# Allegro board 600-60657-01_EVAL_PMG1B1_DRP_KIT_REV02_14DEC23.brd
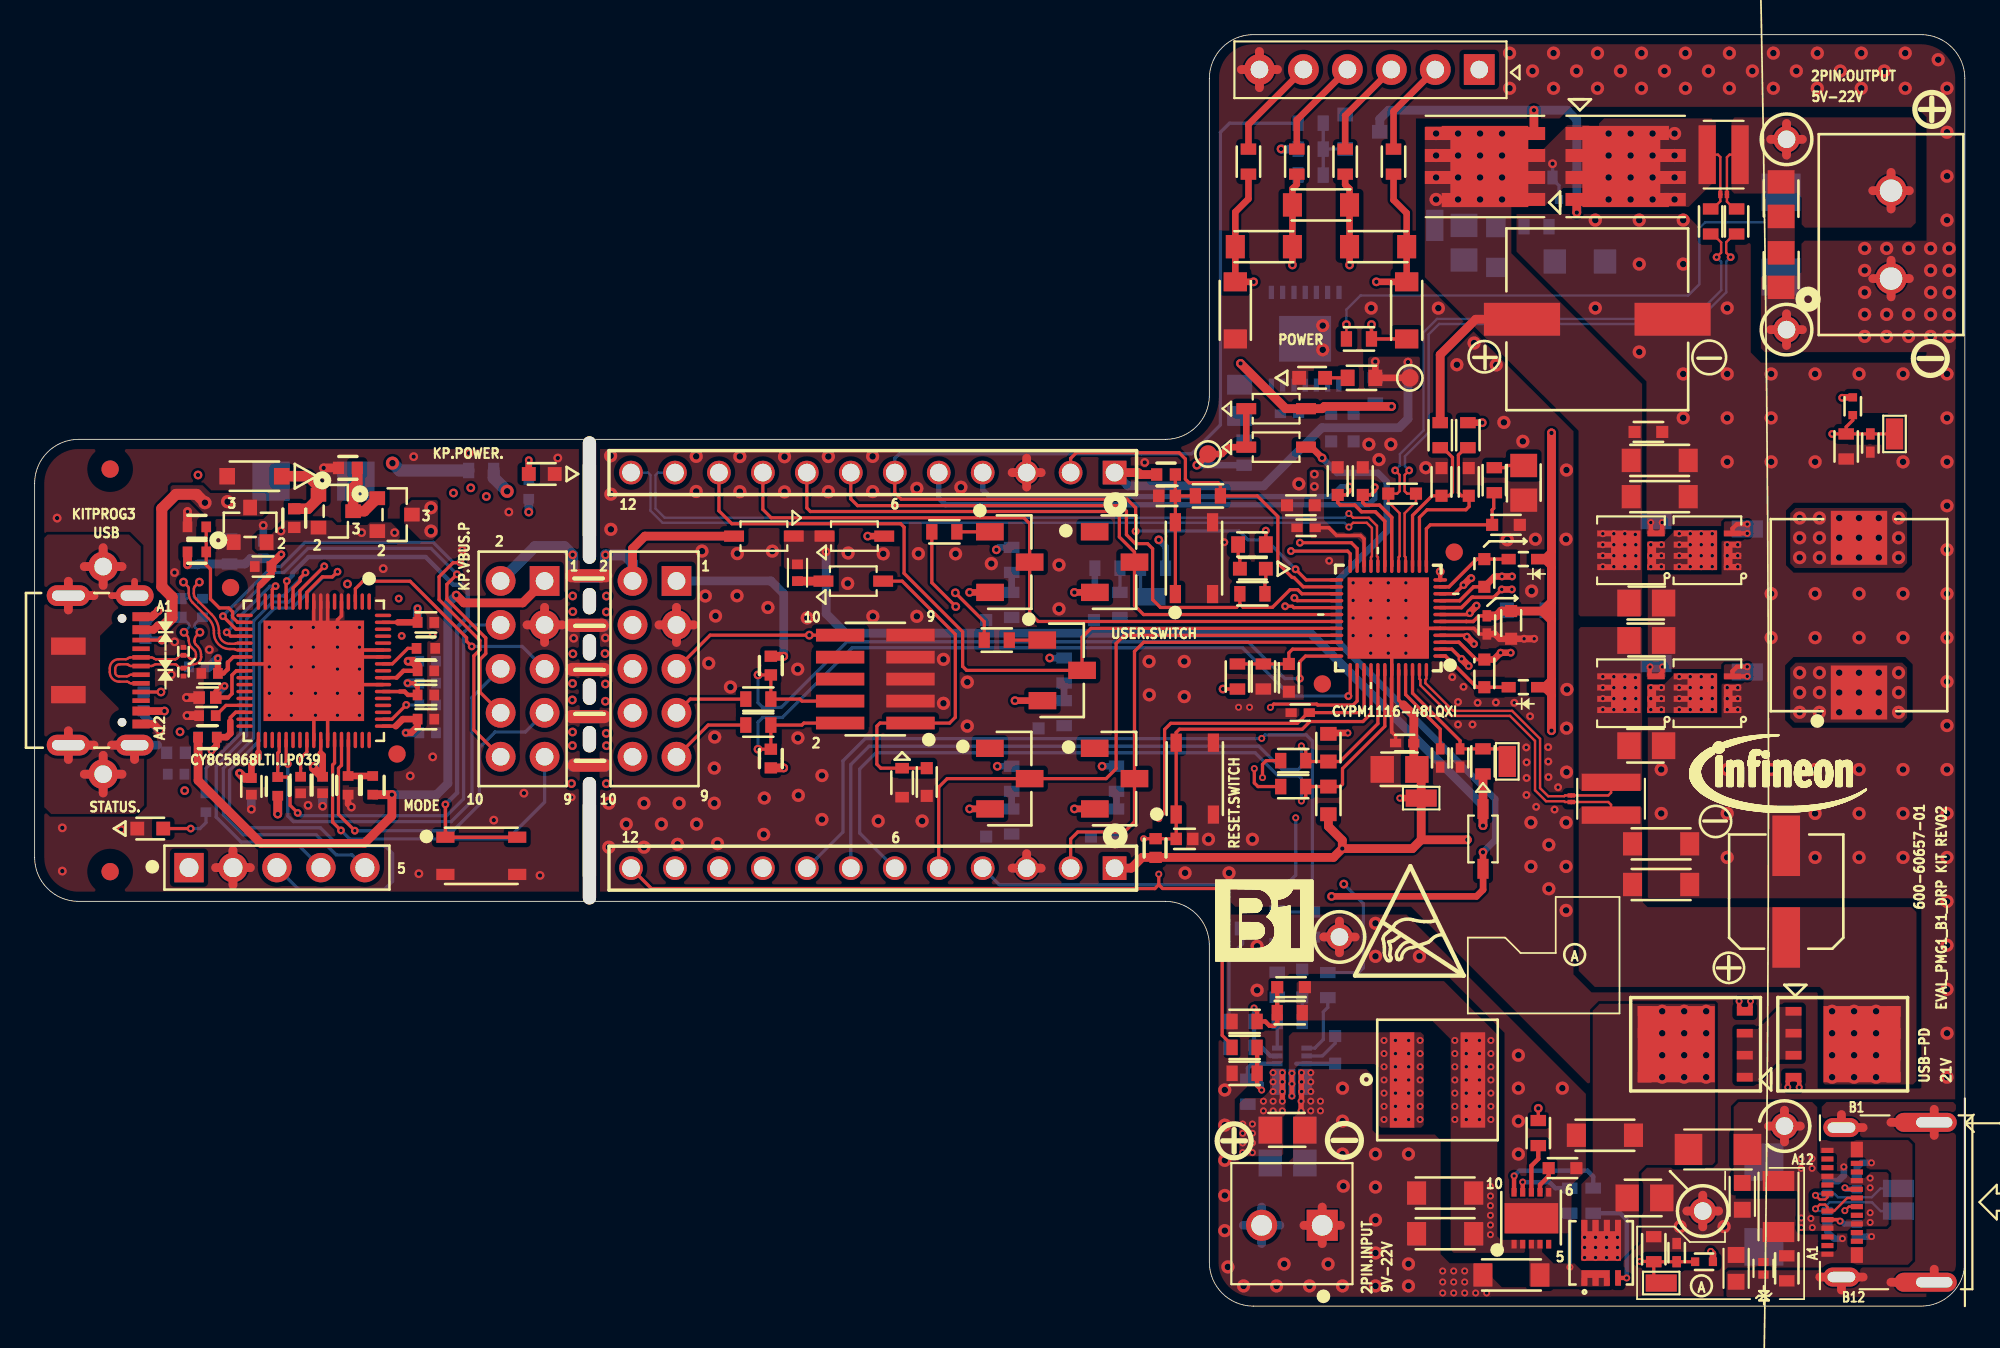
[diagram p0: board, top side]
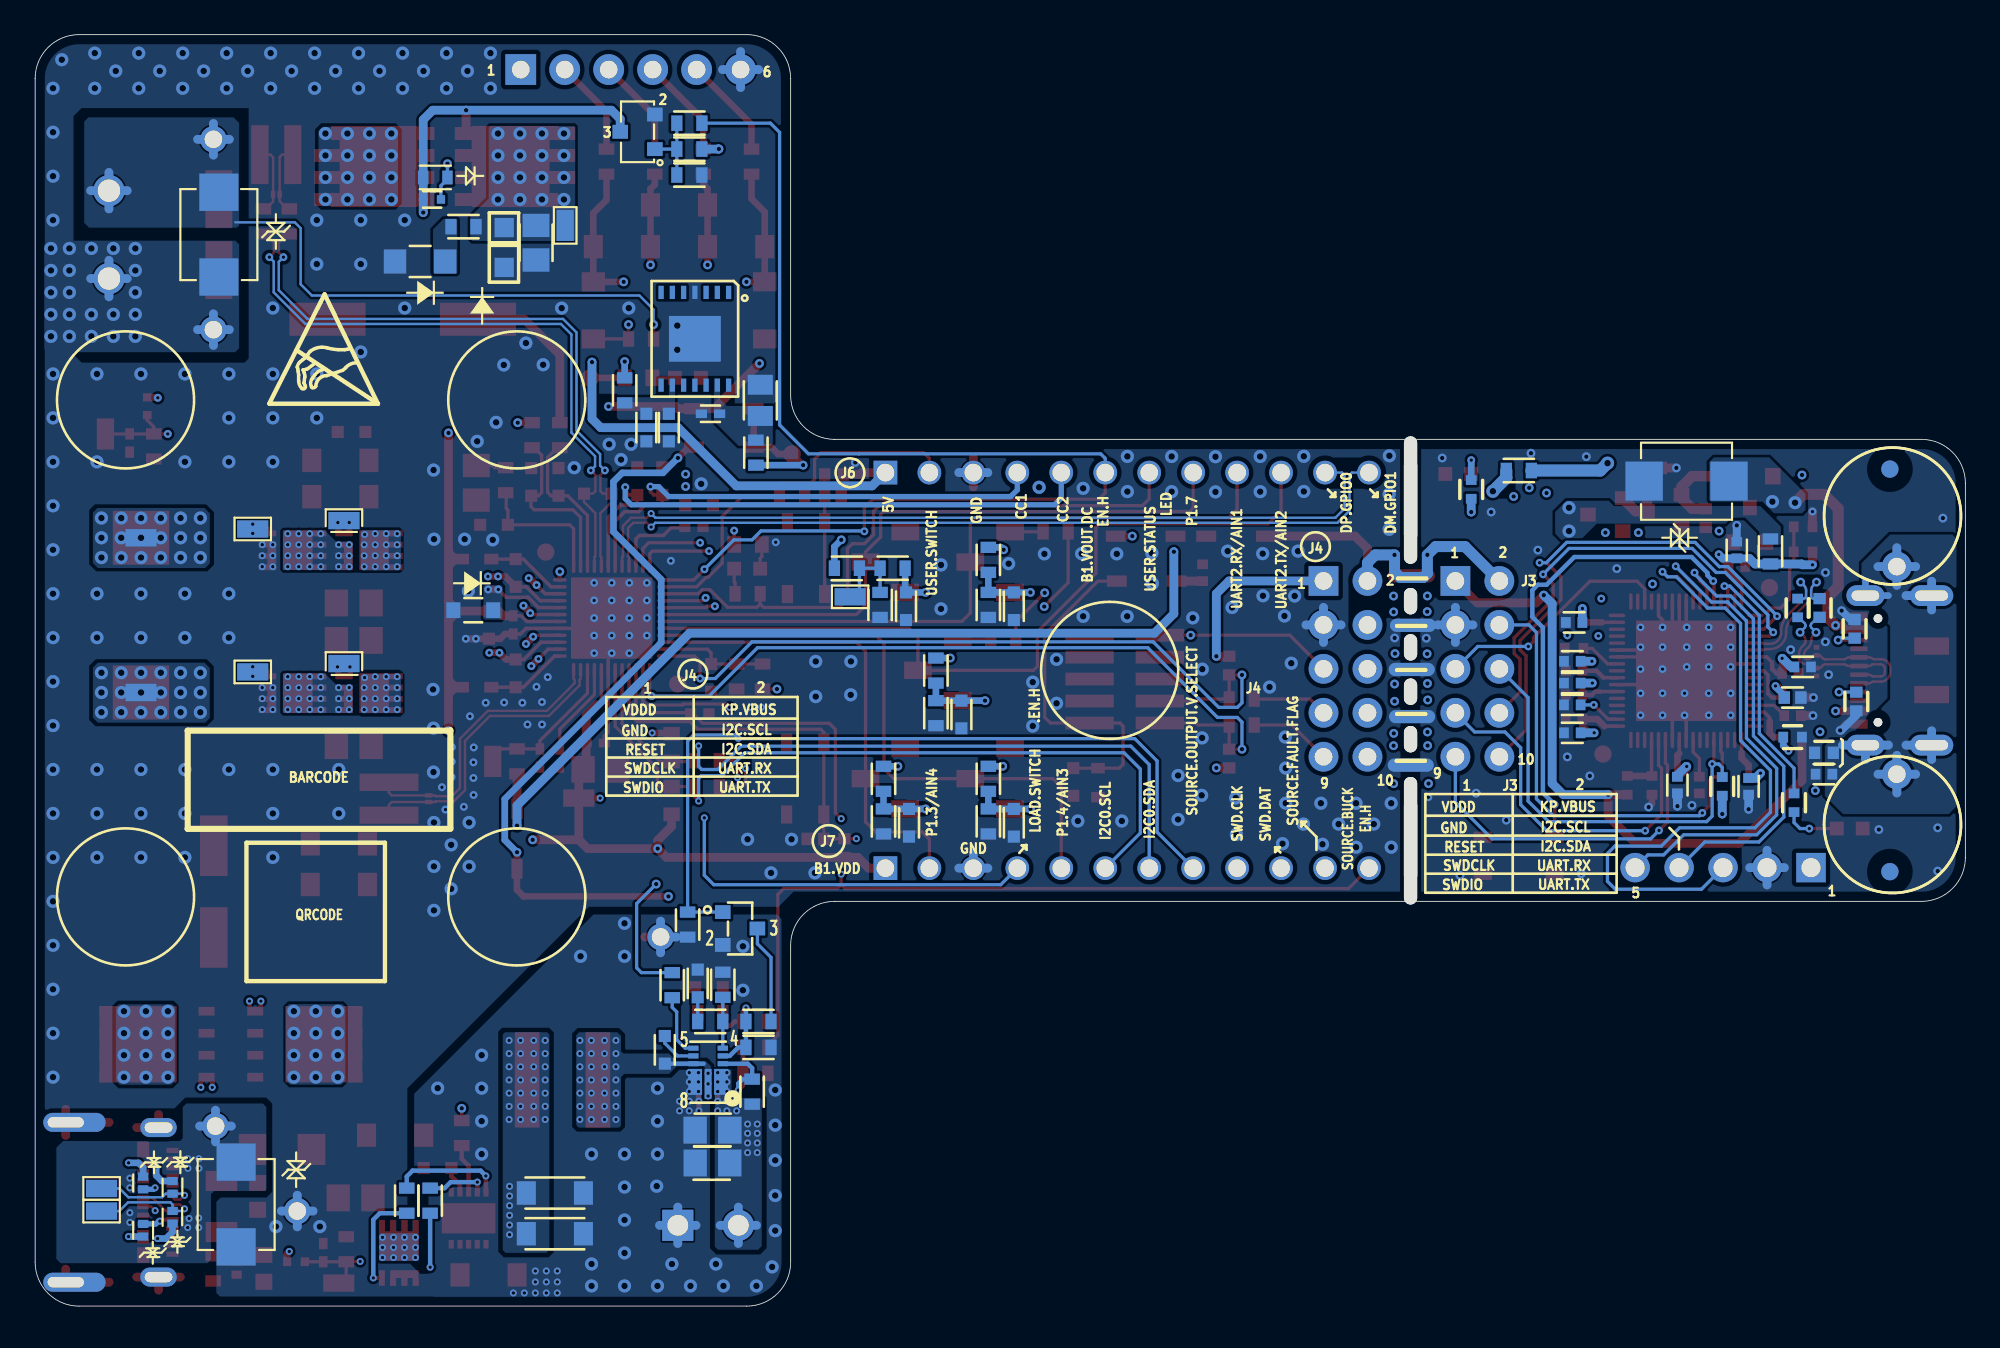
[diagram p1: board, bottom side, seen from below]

Outline 111.52 x 73.48 mm; copper layers: TOP, GND, PWR/SIG, BOTTOM. Coordinates in mm from the lower left corner of the outline.
Outline path: 0,47.55 0,25.93 arc(0.74,24.14) 2.54,23.39 65.33,23.39 arc(67.13,22.65) 67.87,20.85 67.87,2.54 arc(68.62,0.74) 70.41,0 108.98,0 arc(110.78,0.74) 111.52,2.54 111.52,70.94 arc(110.78,72.74) 108.98,73.48 70.41,73.48 arc(68.62,72.74) 67.87,70.94 67.87,52.63 arc(67.13,50.84) 65.33,50.09 2.54,50.09 arc(0.74,49.35) 0,47.55

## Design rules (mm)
constraint set DEFAULT: min track width 0.188, pair gap 0.152
net group CSIOUT_CS_0: nets CSNO CSPO
net group DIFFPAIR0: nets KP_DM KP_DP
net group DIFFPAIR1: nets DM_GPIO1 DP_GPIO0
net group DP1: nets N19965162 N19965164
net group POWER_PH: nets P5LP_VCCD VTARG_MEAS
net group SENSE1: nets IIN_CSN IIN_CSP
net group C: nets UART_CTS
nets with their own width: min track width 0.635; nets KP_VBUS_P P5LP_VDD

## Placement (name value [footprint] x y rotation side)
C1  1.0 uF  [CAPC1005_0402N]  9.98 34.13 180 top
C2  1.0 uF  [CAPC1005_0402N]  10.11 36.57 180 top
C3  0.1uF  [CAPC1005_0402N]  12.52 30.04 270 top
C4  1.0 uF  [CAPC1005_0402N]  13.2 42.74 180 top
C5  1.0 uF  [CAPC1005_0402N]  15.37 30.11 270 top
C6  0.1uF  [CAPC1005_0402N]  16.64 30.11 270 top
C7  0.1uF  [CAPC1005_0402N]  22.61 39.51 0 top
C8  0.1uF  [CAPC1005_0402N]  22.61 36.72 0 top
C9  1.0 uF  [CAPC1005_0402N]  22.71 36.01 0 bottom
C10  1.0 uF  [CAPC1005_0402N]  22.61 33.92 0 top
C11  1uF  [CAPC1608X90N_TY]  51.55 30.29 90 top
C12  0.1uF  [CAPC1005_0402N]  65.43 46.83 0 top
C13  0.1uF  [CAPC1005_0402N]  66.44 27 180 top
C14  0.1uF  [CAPC1608X90N_TY]  74.91 50.77 270 bottom
C15  22uF  [CAPC1608X90N_TY]  76.21 50.77 270 bottom
C16  10uF  [CAPC3216X180N_TDK]  81.49 4.19 180 bottom
C17  1uF  [CAPC1608X90N_TY]  73.16 46.28 180 top
C18  12pF  [CAPC1608X90N_TY]  72.59 18.43 0 top
C19  4.7uF  [CAPC2012X70N_MURATA]  72.39 10.17 0 top
C20  0.1uF  [CAPC1005X56N_CYPS]  73.46 44.98 0 top
C21  0.1uF  [CAPC1005X56N_CYPS]  73.12 34.3 180 top
C22  390pF  [CAPC1608X90N_TY]  75.29 47.68 90 top
C23  0.1uF  [CAPC1005X56N_CYPS]  72.5 51.57 180 bottom
C24  10uF  [CAPC2012_0805N]  69.63 52.35 270 bottom
C25  390pF  [CAPC1608X90N_TY]  76.74 47.68 90 top
C26  10uF  [CAPC2012X70N_MURATA]  78.86 31.02 180 top
C27  0.1uF  [CAPC1608X90N_TY]  79.01 46.96 0 top
C28  0.1uF  [CAPC1005X56N_CYPS]  79.16 32.54 0 top
C29  0.1uF  [CAPC1005X56N_CYPS]  81.21 31.68 90 top
C30  0.1uF  [CAPC1608X90N_TY]  81.28 47.63 90 top
C31  0.1uF  [CAPC1005X56N_CYPS]  82.36 31.68 90 top
C32  10uF  [CAPC3216X180N_TDK]  81.49 6.54 180 top
C33  10uF  [CAPC3216X180N_TDK]  81.49 4.19 180 top
C34  0.1uF  [CAPC1608X90N_TY]  82.86 47.63 90 top
C35  0.1uF  [CAPC1608X90N_TY]  83.76 42.37 270 top
C36  0.1uF  [CAPC1608X90N_TY]  83.76 36.57 270 top
C37  1uF  [CAPC1608X90N_TY]  85.31 39.37 270 top
C38  0.1uF  [CAPC1608X90N_TY]  85.01 45.15 0 top
C39  100nF  [CAPC2012X70N_MURATA]  86.03 47.58 270 top
C40  10uF  [CAPC3216X180N_TDK]  85.33 1.8 180 top
C41  100 pF  [CAPC1608X90N_TY]  88.28 7.98 0 top
C42  1uF  [CAPC2012X70N_MURATA]  93.11 40.63 0 top
C43  1uF  [CAPC2012X70N_MURATA]  93.11 38.47 0 top
C44  1uF  [CAPC2012X70N_MURATA]  93.11 32.39 0 top
C45  0.1uF  [CAPC1608X90N_TY]  93.24 50.52 0 top
C46  10uF  [CAPC3216X180N_TDK]  93.89 48.87 0 top
C47  10uF  [CAPC3216X180N_TDK]  93.89 46.78 0 top
C48  10uF  [CAPC3216X180N_TDK]  93.97 26.71 0 top
C49  10uF  [CAPC3216X180N_TDK]  93.97 24.36 0 top
C50  4.7uF  [CAPC2012X70N_MURATA]  93.01 6.25 0 top
C51  220uF  [CAP_PC_10X12P4_WE]  90.28 57.03 180 top
C52  1nF  [CAPC1005X56N_CYPS]  94.87 3.09 270 top
C53  10nF  [CAPC1608X90N_A]  98.31 2.18 270 top
C54  10nF  [CAPC1608X90N_A]  98.66 6.34 270 top
C55  100uF  [CAP_PC_6P30X8_UCC]  101.2 23.96 270 top
C56  10uF  [CAPC3216X190N_A]  100.76 5.76 270 top
C57  1uF  [CAPC2012X70N_MURATA]  100.91 63.97 270 top
C58  1uF  [CAPC2012X70N_MURATA]  100.91 59.88 270 top
C59  1nF  [CAPC1005X56N_CYPS]  106.06 49.88 90 top
C60  10uF  [CAPC3216X180N_TDK]  81.49 6.54 180 bottom
C61  0.1uF  [CAPC1608X90N_TY]  75.14 14.81 90 bottom
C62  1.2nF  [CAPC1608X90N_TY]  73.24 18.65 90 bottom
C63  4.7uF  [CAPC2012X70N_MURATA]  72.39 10.17 0 bottom
C64  4.7uF  [CAPC2012X70N_MURATA]  72.39 8.27 0 bottom
C65  1.0 uF  [CAPC1005_0402N]  22.61 39.51 0 bottom
C66  1.0 uF  [CAPC1005_0402N]  22.71 37.27 0 bottom
C67  0.1uF  [CAPC1005_0402N]  22.61 35.32 0 top
C68  1.0 uF  [CAPC1005_0402N]  22.71 33.13 0 bottom
C69  1.0 uF  [CAPC1005_0402N]  22.71 34.75 0 bottom
C70  0.1uF  [CAPC1005_0402N]  16.64 30.11 270 bottom
C71  0.1uF  [CAPC1005_0402N]  13.21 43.69 90 bottom
C72  1.0 uF  [CAPC1005_0402N]  12.52 30.04 270 bottom
C73  0.1uF  [CAPC1005_0402N]  9.4 36.94 180 bottom
C74  10nF  [CAPC1005_0402N]  8.17 30.74 0 bottom
C75  0.1uF  [CAPC1005X56N_CYPS]  83.9 39.37 90 top
C76  1.0 uF  [CAPC1005_0402N]  9.98 35.17 180 bottom
C77  0.1uF  [CAPC1005_0402N]  9.98 35.17 180 top
C78  1uF  [CAPC2012X70N_MURATA]  82.58 61.46 270 bottom
C79  10nF  [CAPC1608X90N_TY]  54.98 40.45 270 bottom
C80  10nF  [CAPC1608X90N_TY]  58 34.19 270 bottom
C81  10nF  [CAPC1608X90N_TY]  54.98 27.94 270 bottom
C82  10nF  [CAPC1608X90N_TY]  61.03 27.94 270 bottom
C83  10nF  [CAPC1608X90N_TY]  72.47 36.31 270 top
C84  0.1uF  [CAPC1608X90N_TY]  61.21 40.45 270 bottom
C85  0.1uF  [CAPC3216X180N_TDK]  77.62 61.23 180 top
C86  0.1uF  [CAPC3216X180N_TDK]  74.32 63.64 180 top
C87  0.1uF  [CAPC3216X180N_TDK]  71.02 61.23 180 top
C88  0.1uF  [CAPC3216X180N_TDK]  69.37 57.55 270 top
C89  0.1uF  [CAPC3216X180N_TDK]  79.27 57.55 90 top
C90  10uF  [CAPC3216X180N_TDK]  90.73 9.88 180 top
D1  ESD131-B1-W0201  [ESD0201_CANTRON]  8.6 37.84 270 top
D2  ESD131-B1-W0201  [ESD0201_CANTRON]  8.6 36.64 90 top
D3  MMSZ5230C-E3-08  [SOD-123_DI]  12.7 47.96 0 top
D4  CMHSH5-4 TR PBFREE  [DIO2_SOD123N]  42.14 44.5 180 top
D5  CMHSH5-4 TR PBFREE  [DIO2_SOD123N]  47.36 44.5 0 top
D6  CMHSH5-4 TR PBFREE  [DIO2_SOD123N]  47.3 41.9 0 top
D7  -  [BZT52C24T-7]  88.4 65.23 0 bottom
D8  RB510SM-40T2R  [SOD-523]  86.01 43.17 0 top
D9  RB510SM-40T2R  [SOD-523]  86.01 35.77 0 top
D10  SZESD7241N2T5G  [DIODFN100X60X45-2N]  99.88 2.18 90 top
D11  SZESD7241N2T5G  [DIODFN100X60X45-2N]  103.58 5.13 90 bottom
D12  SZESD7241N2T5G  [DIODFN100X60X45-2N]  103.58 6.86 270 bottom
D13  SZESD7241N2T5G  [DIODFN100X60X45-2N]  105.28 7.11 270 bottom
D14  SZESD7241N2T5G  [DIODFN100X60X45-2N]  105.28 4.38 90 bottom
D15  SMBJ24CA  [DIOM5336X262N]  100.91 61.92 90 bottom
D16  SMBJ24CA  [DIOM5336X262N]  99.91 5.87 90 bottom
D17  CMHSH5-4 TR PBFREE  [DIO2_SOD123N]  83.68 27 270 top
D18  CMHSH5-4 TR PBFREE  [DIO2_SOD123N]  71.73 49.64 0 top
D19  CMHSH5-4 TR PBFREE  [DIO2_SOD123N]  71.73 51.86 0 top
D20  SMBJ24CA  [DIOM5336X262N]  16.11 47.67 180 bottom
D21  BZD27B22P-M3-08  [DO-219AB]  89.28 60.37 180 bottom
D22  DF2S23P2FU  [SOD-323]  84.42 61.18 90 bottom
D23  PLZ24B-G3/H  [DO-219AC]  86.21 40.22 180 bottom
DM_GPIO1  SMD  [SMDTP]  107.68 6.8 180 bottom
DP_GPIO0  SMD  [SMDTP]  107.68 5.49 180 bottom
FB1  50 OHMS@100MHz  [IND1206N]  97.26 9.05 180 top
HG1  SMD  [SMDTP]  93.68 37.14 180 bottom
HG2  SMD  [SMDTP]  93.68 45.4 180 bottom
J1  DX07S016JA3R1500  [JAE_DX07S016JA3R1500]  2.8 36.74 270 top
J2  5 PIN PROG  [WURTH_61300511121]  8.92 25.34 0 top
J3  CON 5x2  [SULLINS_PPPC052LFBN-RC]  29.47 41.91 270 top
J4  CON 5x2  [SULLINS_PPPC052LFBN-RC]  37.09 41.91 270 top
J6  TSW-112-14-G-S  [SAMTEC_TSW-112-14-G-S]  62.4 48.17 180 top
J7  TSW-112-14-G-S  [SAMTEC_TSW-112-14-G-S]  62.4 25.31 180 top
J8  50MIL KEYED SMD  [SAMTEC_FTSH-105-01-L-DV-K]  50.6 33.7 90 top
J9  691213510002  [CONN_691213510002_WRE]  107.26 59.38 90 top
J10  2012670005  [MOLEX_2012670005]  111.52 6 90 top
J11  691103110002  [TE_1776275-2]  74.39 4.67 180 top
J13  61300611121  [BERG_2P54P_1X6N]  77.18 71.45 270 top
JMP1  USB_Hold  [CON_RA_STIFF_850P_TYPEC]  3.96 30.74 90 top
L1  15uH  [IND_XGL6060-682MEC_COC-M]  81.05 13.07 0 top
L2  6.8uH  [MPX1D1040L6R8]  105.41 39.93 90 top
LED1  AMBER LED  [LEDC1608_0603N]  6.68 27.6 180 top
LED2  AMBER LED  [LEDC1608_0603N]  29.3 48.09 0 top
LED3  GREEN  [LEDC1608X80N_G]  70.38 42.62 0 top
LED4  GREEN  [LEDC1608X80N_G]  73.81 53.65 180 top
LG1  SMD  [SMDTP]  98.95 36.65 0 bottom
LG2  SMD  [SMDTP]  98.95 44.91 180 bottom
NOREF  -  []  6.1 41.21 0 top
NOREF#2  -  []  0.51 24.41 0 top
NOREF#3  -  []  2.54 50.09 0 top
NOREF#4  -  [unnamed#2]  32.06 40.74 0 top
NOREF#5  -  []  8.16 37.21 0 top
NOREF#6  -  []  69.56 70.07 0 top
NOREF#7  -  []  0 25.93 90 top
NOREF#8  -  [unnamed#2]  32.06 45.95 0 top
NOREF#9  -  [unnamed#2]  32.06 38.07 0 top
NOREF#10  -  [unnamed#2]  32.06 47.22 0 top
NOREF#11  -  [unnamed#2]  32.06 26.26 0 top
NOREF#12  -  []  70.41 0 0 top
NOREF#13  -  []  5.05 33.74 90 top
NOREF#14  -  []  15.04 34.61 90 top
NOREF#15  -  [unnamed#2]  32.06 27.53 0 top
NOREF#16  -  []  -317.2 -204.42 0 top
NOREF#17  -  []  94.53 76.73 0 top
NOREF#18  -  []  1.95 41.06 0 top
NOREF#19  -  [unnamed#2]  32.06 32.77 0 top
NOREF#20  -  []  8.46 37.55 90 top
NOREF#21  -  []  1.95 35.34 90 top
NOREF#22  -  []  1.95 32.42 90 top
NOREF#23  -  []  80.93 71.46 0 top
NOREF#24  -  []  2.54 23.39 0 top
NOREF#25  -  []  8.74 36.93 90 top
NOREF#26  -  [unnamed#2]  32.06 35.51 0 top
NOREF#27  -  []  70.41 73.48 0 top
NOREF#28  -  []  8.6 37.61 90 top
NOREF#29  -  []  -16.36 -25.12 0 top
NOREF#30  -  []  69.56 70.07 90 top
NOREF#31  -  []  110.41 73.04 0 top
NOREF#32  -  []  111.52 2.54 90 top
NOREF#33  -  []  8.6 36.41 90 top
NOREF#34  -  []  87.88 38.79 0 top
NOREF#35  -  []  7.88 37.83 0 top
NOREF#36  -  [unnamed#2]  4.36 48.37 90 top
NOREF#37  -  [unnamed#2]  4.36 25.11 270 top
NOREF#38  -  [unnamed#2]  4.36 25.11 90 bottom
NOREF#39  -  [unnamed#2]  4.36 48.37 270 bottom
NOREF#40  -  []  12.85 31.29 180 bottom
NTC0  R, NTC  [RESC1608X55N_PEC]  93.55 3.29 270 top
NTC1  R, NTC  [RESC1608X55N_PEC]  104.66 49.68 90 top
NTCP0  SMD  [SMDTP]  93.98 1.33 180 top
NTCP1  SMD  [SMDTP]  107.46 50.41 270 top
Q1  BSS308PEH6327XTSA1  [SOT95P240X111-3N]  12.45 45.15 0 top
Q2  BSS308PEH6327XTSA1  [SOT95P240X111-3N]  17.4 45.94 270 top
Q3  BSS308PEH6327XTSA1  [SOT95P240X111-3N]  20.8 45.74 270 top
Q4  -  [2N7002H6327XTSA2]  76.72 67.87 90 bottom
Q5  BSC084P03NS3GATMA1  [BSC030P03NS3]  83.8 65.86 180 top
Q6  BSZ0589NSATMA1  [PG-TSDSON-8-33]  90.51 3.08 90 top
Q7  -  [BSZ063N04LS6]  92.23 43.68 180 top
Q8  -  [BSZ063N04LS6]  92.23 35.42 180 top
Q9  BSC084P03NS3GATMA1  [BSC030P03NS3]  91.92 65.86 0 top
Q10  -  [BSZ063N04LS6]  96.65 43.68 180 top
Q11  -  [BSZ063N04LS6]  96.65 35.42 180 top
Q12  ISC045N03L5SATMA1  [IFX-PG-TDSON-8-6-V]  95.91 15.14 180 top
Q13  ISC045N03L5SATMA1  [IFX-PG-TDSON-8-6-V]  104.51 15.14 0 top
Q14  2N7002H6327XTSA2  [SOT23_1_2_3]  70.79 21.82 270 bottom
R1  30K  [RESC1005_0402M]  9.37 45.04 0 top
R2  15K  [RESC1005_0402M]  9.37 43.59 0 top
R3  1M  [RESC1005_0402M]  9.98 32.88 0 top
R4  4.7K  [RESC1005_0402M]  14.05 30.04 270 top
R5  1K  [RESC1005_0402M]  15 45.54 270 top
R6  10K  [RESC1005_0402M]  18.1 48.44 180 top
R7  49.9K  [RESC1005_0402M]  18.11 30.1 90 top
R8  49.9K  [RESC1005_0402M]  19.53 30.1 90 top
R9  100K  [RESC1005_0402M]  22.61 38.01 180 top
R10  0 OHM  [RESC1608_0603N]  41.81 35.08 0 top
R11  0 OHM  [RESC1608_0603N]  41.81 33.58 0 top
R12  2.2K  [RESC1005_0402M]  42.54 37.02 90 top
R13  2.2K  [RESC1005_0402M]  42.54 31.64 270 top
R14  0OHM  [RESC1005X40N_PEC]  44.07 42.38 90 top
R15  10K  [RESC1608X55N_PEC]  69.91 16.45 180 top
R16  10K  [RESC1608X55N_PEC]  69.91 13.45 180 top
R17  0 OHM  [RESC1608_0603N]  67.79 46.83 180 top
R18  330E  [RESC1608X55N_A]  70.33 44.02 180 top
R19  4.7K  [RESC1005_0402M]  64.77 26.47 90 top
R20  4.7K  [RESC1005_0402M]  65.37 48.06 0 top
R21  0 OHM  [RESC1608_0603N]  70.36 41.17 0 top
R22  0E  [RESC1608X55N_PEC]  69.91 14.95 0 top
R25  0 OHM  [RESC1608_0603N]  52.56 44.75 0 top
R26  0 OHM  [RESC1608_0603N]  55.59 38.49 0 top
R27  0E  [RESC1608_0603N]  77.46 52.92 270 bottom
R28  330E  [RESC1608X55N_A]  76.66 53.65 180 top
R29  165K  [RESC1608X55N_PEC]  72.52 16.96 180 top
R30  0 OHM  [RESC1608_0603N]  72.72 31.52 0 top
R31  0 OHM  [RESC1608_0603N]  72.72 30.03 0 top
R32  0E  [RESC1608_0603N]  69.88 49.32 270 bottom
R33  100E  [RESC1608X55N_PEC]  73.72 68.37 180 bottom
R34  2.2K  [RESC1608X55N_A]  74.75 32.27 90 top
R35  2.2K  [RESC1608X55N_A]  74.75 29.23 270 top
R36  10K  [RESC1608X55N_PEC]  73.72 66.87 180 bottom
R38  10K  [RESC1608X55N_PEC]  73.72 65.37 180 bottom
R39  0E  [RESC1608X55N_PEC]  81.21 50.33 270 top
R40  0E  [RESC1608X55N_PEC]  82.81 50.33 270 top
R41  0E  [RESC1608X55N_PEC]  83.68 31.48 90 top
R42  100E  [RESC1608X55N_PEC]  84.34 47.73 90 top
R43  49.9K  [RESC1005X40N_PEC]  88.59 63.96 0 bottom
R44  0E  [RESC1608X55N_PEC]  86.88 10 270 top
R45  0.005  [SUSUMU-KRL3216]  91.08 29.32 270 top
R46  4.02K  [RESC1005X40N_PEC]  96.45 2.56 180 top
R47  0E  [RESC1608X55N_PEC]  96.83 62.69 90 top
R48  0.005  [SUSUMU-KRL3216]  97.58 66.55 0 top
R49  0E  [RESC1608X55N_PEC]  98.33 62.69 90 top
R50  100K  [RESC1608X55N_PEC]  101.23 2.18 270 top
R51  4.02K  [RESC1005X40N_PEC]  105.05 52.01 270 top
R52  0E  [RESC1608X55N_PEC]  90.05 6.09 90 bottom
R53  39 OHM  [RESC1608X55N_PEC]  88.7 6.09 270 bottom
R54  0E  [RESC1608X55N_PEC]  74.71 18.55 270 bottom
R55  10K  [RESC1608X55N_PEC]  73.82 22.05 270 bottom
R56  34K  [RESC1608X55N_PEC]  72.52 16.45 180 bottom
R57  12pF  [RESC1608X55N_PEC]  71.79 18.57 270 bottom
R58  0603  [RESC1608X55N_PEC]  70.1 12.39 270 bottom
R59  34K  [RESC1608X55N_PEC]  69.73 16.45 180 bottom
R60  30K  [RESC1608X55N_PEC]  69.73 14.95 180 bottom
R61  2.2K  [RESC1005_0402M]  28.55 47.2 90 bottom
R62  0 OHM  [RESC1608_0603N]  25.8 48.29 0 bottom
R63  4.7K  [RESC1005_0402M]  14.05 30.04 270 bottom
R64  0ohm  [RESC1608_0603N]  11.26 43.61 90 bottom
R65  2M  [RESC1005_0402M]  9.98 32.88 0 bottom
R66  2.2K  [RESC1005_0402M]  9.9 29.09 270 bottom
R67  22E  [RESC1005_0402M]  9.69 40.35 90 bottom
R68  22E  [RESC1005_0402M]  8.42 40.35 90 bottom
R69  100K  [RESC1005_0402M]  8.17 31.98 0 bottom
R70  5.1K  [RESC1005_0402M]  6.4 39.14 270 bottom
R71  5.1K  [RESC1005_0402M]  6.3 34.94 90 bottom
R72  1K  [RESC1608X55N_PEC]  86.77 62.38 180 bottom
R73  12K  [RESC1608X55N_PEC]  56.45 43.13 270 bottom
R74  10K  [RESC1608X55N_PEC]  56.45 40.52 270 bottom
R75  34K  [RESC1608X55N_PEC]  59.48 36.73 270 bottom
R76  10K  [RESC1608X55N_PEC]  59.48 34.27 270 bottom
R77  56K  [RESC1608X55N_PEC]  56.45 30.48 270 bottom
R78  10K  [RESC1608X55N_PEC]  56.45 28.01 270 bottom
R79  78.7K  [RESC1608X55N_PEC]  62.51 30.48 270 bottom
R80  10K  [RESC1608X55N_PEC]  62.51 28.01 270 bottom
R81  100K  [RESC1608X55N_PEC]  69.49 36.39 90 top
R82  10K  [RESC1608X55N_PEC]  70.99 36.39 270 top
R83  6.65K  [RESC1608X55N_PEC]  64.62 42.64 180 bottom
R84  1K  [RESC1608X55N_PEC]  61.98 42.64 0 bottom
R85  953E  [RESC1608X55N_PEC]  62.7 40.52 90 bottom
R86  1K  [RESC1608X55N_PEC]  78.51 66.14 90 top
R87  1K  [RESC1608X55N_PEC]  75.72 66.14 90 top
R88  1K  [RESC1608X55N_PEC]  72.92 66.14 90 top
R89  1K  [RESC1608X55N_PEC]  70.13 66.14 90 top
R90  1K  [RESC1608X55N_PEC]  76.52 55.9 180 top
SP1  NetShort2  [NETSHORT2]  88.78 29.51 180 top
SP2  NetShort2  [NETSHORT2]  88.78 29.13 180 top
SP3  NetShort2  [NETSHORT2]  97.39 64.25 90 top
SP4  NetShort2  [NETSHORT2]  97.77 64.25 90 top
SW1  434123025826  [SW_SKRPACE010]  25.81 26.02 0 top
SW2  PTS810 SJG 250 SMTR LFS  [SW_SKRPACE010]  66.98 43.23 90 top
SW3  434123025826  [SW_SKRPACE010]  67.03 30.49 90 top
SW4  -  [CAS-120A]  56.34 43 270 top
SW5  -  [CAS-120A]  59.37 36.74 270 top
SW6  -  [CAS-120A]  56.34 30.49 270 top
SW7  -  [CAS-120A]  62.4 30.49 270 top
SW8  -  [CAS-120A]  62.4 43 270 top
SW_1  SMD  [SMDTP]  105.41 35.46 180 bottom
SW_2  SMD  [SMDTP]  105.41 44.4 180 bottom
TP2  TP_SMD  [TP102C]  79.45 53.64 0 top
TP3  BLACK  [TP-43R_S_B]  75.39 21.33 0 top
TP4  SMD  [SMDTP]  80.11 29.36 0 top
TP5  TP_SMD  [TP102C]  67.8 49.24 0 top
TP6  SMD  [SMDTP]  85.08 31.48 90 top
TP7  BLACK  [TP-43R_S_B]  96.38 5.5 0 top
TP8  RED  [TP-43R_S_R]  101.1 10.41 0 top
TP9  BLACK  [TP-43R_S_B]  101.22 56.43 0 top
TP10  RED  [TP-43R_S_R]  101.22 67.43 0 top
TP11  SMD  [SMDTP]  64.43 40.99 180 bottom
TVS1  ESD3V3D5-TP  [SODFL1608X77M]  50.12 30.25 90 top
U1  CY8C5868LTI-LP039  [QFN40P800X800X100-69M]  16.13 36.72 270 top
U2  TLE42744EV50  [SOP65P500X400X170-15N]  73.41 55.9 0 bottom
U3  CYPM1116-48LQXI  [QFN40P600X600X60-49N]  78.21 39.77 180 top
U4  STELPD01PUR  [DFN50P300X300X100-11N_B]  86.48 5.08 90 top
U5  AP63357  [DFN45P200X300X85-9L]  72.64 13.64 0 bottom
UNK*  -  []  4.21 45.66 180 bottom
UNK*#2  -  []  83.69 23.65 180 bottom
UNK*#3  -  []  83.69 52.37 180 bottom
UNK*#4  -  []  106.3 23.65 180 bottom
UNK*#5  -  []  106.3 52.37 180 bottom
UNK*#6  -  []  49.44 36.74 180 bottom
UNK*#7  -  []  4.21 27.83 180 bottom
VOUT  SMD  [SMDTP]  80.9 62.46 270 bottom

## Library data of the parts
C1-C10 C12-C14 C24 C65-C74 C76 C77 = CAPACITOR NON-POL
C11 = CAP-NP_0
C15 = C_np
C16 C18-C22 C25-C50 C52-C54 C56-C64 C75 C78-C83 C85-C90 = CAP
C17 C84 = 0_0.01uF-50V-10%-X7R-0603
C23 = CAP NP
C51 C55 = CAP_P_ALT
D1 D2 = BZX84C18/SOT_1
D3 = DIO-ZENER_3
D4-D6 D17-D19 = DIO STKY PMEG3020_0: User Part Number: Part No
D7 D8 = DIODE SCHOTTKY_5
D9 = DIODE SCHOTTKY_4
D10-D16 D20 = DIODE TVS BI-DIR
D21 = DIODE SCHOTTKY_1
D22 = DIODE SCHOTTKY_0
D23 = DIODE SCHOTTKY_3
DM_GPIO1 DP_GPIO0 HG1 HG2 LG1 LG2 NTCP0 NTCP1 SW_1 SW_2 TP2-TP11 VOUT = TEST_POINT
FB1 = FERRITEBEAD_ALT1
J1 = USB MICRO R/A DIP_5
J2 = HEADER 5_0
J3 J4 = RECPT 4X2 100MIL_5
J6 J7 = HEADER 12_0
J8 = 10 Pin Header 50mil Keyed SMD
J9 = CON2: User Part Number: PN; Tolerance: TOL
J10 = USB-PD_TYPE-C_1
J11 = CON2
J13 = CON6
JMP1 = USB_JUMP_0
L1 = XAL1010-472ME: User Part Number: PN; Tolerance: TOL
L2 = XAL1010-472ME
LED1 LED2 = LED_2
LED3 LED4 = LED_GREEN2_0603
NTC0 NTC1 = RESISTOR VAR 2
Q1-Q3 = FET-MOS-P_1
Q4 = 2N7002H6327XTSA2_0
Q5 Q9 = MOSFET_P_SO8
Q6 = BSC059N04LS G_0: User Part Number: PN; Tolerance: TOL
Q7 Q8 Q10 Q11 = 5P_N-CH_TYPE1C
Q12 Q13 = MOSFET_P_SO8_0
Q14 = 2N7002H6327XTSA2
R1-R4 R7-R9 R12 R13 R19 R20 R61 R63-R69 = RESISTOR
R5 R6 R10 R11 R15-R17 R21 R22 R25 R26 R29-R31 R33 R36 R38 R42 R44-R60 R62 R70-R90 = RES
R14 R27 R32 R39-R41 R43 = R
R18 R28 R34 R35 = RESD,0402,5%,1/32W,10K: tolerance: 5%
SP1-SP4 = NetShort2
SW1-SW3 = SW PUSH NO 4-PIN
SW4-SW8 = SW_T_SPDT_1
TVS1 = TVS 5V SOD-323_0
U1 = CY8C38***-QFN68_0
U2 = TLE42744EV50
U3 = PMG1-B1_17
U4 = STELPD01PUR
U5 = AP63357_1

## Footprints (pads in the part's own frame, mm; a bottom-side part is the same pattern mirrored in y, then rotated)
2N7002H6327XTSA2
  rect 0.8x0.9 smd: 1(-1,-1) 2(1,-1) 3(0,1)
BERG_2P54P_1X6N
  rect 1.778x1.778 hole 1.016: 1(-0.013,6.287)
  round 1.778 hole 1.016: 2(-0.013,3.747) 3(-0.013,1.206) 4(-0.013,-1.333) 5(-0.013,-3.873) 6(-0.013,-6.413)
BSC030P03NS3
  rect 1.3x0.75 smd: 1(-2.825,1.905) 2(-2.825,0.635) 3(-2.825,-0.635) 4(-2.825,-1.905) 5(2.825,-1.905) 6(2.825,-0.635) 7(2.825,0.635)
  custom 1.173x1.173 smd: 8(0,0)
BSZ063N04LS6
  rect 1x0.34 smd: 1(-1.45,0.975) 2(-1.45,0.325) 4(-1.45,-0.975)
  custom 0.25x0.25 smd: 3(-1.45,0.325)
  custom 0.573x0.573 smd: 5(0.695,0)
BZT52C24T-7
  rect 0.6x0.8 smd: 1(-0.7,0) 2(0.7,0)
CAP_PC_6P30X8_UCC
  rect 3.5x1.6 smd: 1(2.65,0) 2(-2.65,0)
CAP_PC_10X12P4_WE
  rect 4.4x1.9 smd: 1(4.35,0) 2(-4.35,0)
CAPC1005_0402N
  rect 0.56x0.62 smd: 1(-0.48,0) 2(0.48,0)
CAPC1005X56N_CYPS
  rect 0.65x0.5 smd: 1(-0.526,0) 2(0.526,0)
CAPC1608X90N_A
  rect 0.92x0.97 smd: 1(-0.775,0) 2(0.775,0)
CAPC1608X90N_TY
  rect 0.7x0.7 smd: 1(-0.8,0) 2(0.8,0)
CAPC2012_0805N
  rect 1.15x1.45 smd: 1(-0.9,0) 2(0.9,0)
CAPC2012X70N_MURATA
  rect 1.35x1.55 smd: 1(-1,0) 2(1,0)
CAPC3216X180N_TDK
  rect 1.1x1.35 smd: 1(-1.65,0) 2(1.65,0)
CAPC3216X190N_A
  rect 1.16x1.82 smd: 1(-1.475,0) 2(1.475,0)
CAS-120A
  rect 1x1.6 smd: 1(-1.75,-1.15) 2(0,1.15) 3(1.75,-1.14)
CON_RA_STIFF_850P_TYPEC
  round 1.72 hole 1.02: 1(0,0) 2(12,0)
CONN_691213510002_WRE
  round 1.803 hole 1.295: 1(0,0) 2(5.08,0)
DFN45P200X300X85-9L
  rect 0.8x1.5 smd: 1(-0.75,0.675) 8(0.75,0.675)
  rect 0.6x0.3 smd: 2(-0.85,-0.375) 3(-0.85,-0.825) 4(-0.85,-1.275) 5(0.85,-1.275) 6(0.85,-0.825) 7(0.85,-0.375)
  rect 0.4x1.73 smd: 9(0,0.79)
DFN50P300X300X100-11N_B
  rect 0.5x0.3 smd: 1(-1.5,1) 2(-1.5,0.5) 3(-1.5,0) 4(-1.5,-0.5) 5(-1.5,-1) 6(1.5,-1) 7(1.5,-0.5) 8(1.5,0) 9(1.5,0.5) 10(1.5,1)
  rect 1.75x3.1 smd: 11(0,0)
DIO2_SOD123N
  rect 1.15x0.65 smd: A(1.725,0) K(-1.725,0)
DIODFN100X60X45-2N
  rect 0.47x0.6 smd: 1(-0.365,0) 2(0.365,0)
DIOM5336X262N
  rect 2.16x2.26 smd: 1(-2.45,0) 2(2.45,0)
DO-219AB
  rect 1.295x1.397 smd: 1(-1.45,0) 2(1.45,0)
DO-219AC
  rect 0.813x0.914 smd: 1(-1.15,0) 2(1.15,0)
ESD0201_CANTRON
  rect 0.279x0.322 smd: 1(-0.229,0) 2(0.229,0)
IFX-PG-TDSON-8-6-V
  rect 0.925x0.5 smd: 1(-2.894,1.905) 2(-2.894,0.635) 3(-2.894,-0.635) 4(-2.894,-1.905)
  rect 0.8x0.6 smd: 5(2.894,-1.905) 6(2.894,-0.635) 7(2.894,0.635) 8(2.894,1.905)
IND1206N
  rect 1.6x1.8 smd: 1(-1.7,0) 2(1.7,0)
IND_XGL6060-682MEC_COC-M
  rect 1.422x5.512 smd: 1(-2.045,0) 2(2.045,0)
JAE_DX07S016JA3R1500
  round 0.5 hole 0.6 unplated: (-3,2.25)
  oval 0.5x0.5 hole 0.85x0.6 unplated: (3,2.25)
  rect 0.52x1 smd: A1(-3.1,3.35) A4(-2.35,3.35) B1(3.1,3.35) B4(2.35,3.35)
  rect 0.27x1 smd: A5(-1.75,3.35) A6(-0.25,3.35) A7(0.75,3.35) A8(1.75,3.35) B5(1.25,3.35) B6(0.25,3.35) B7(-0.75,3.35) B8(-1.25,3.35)
  oval 1.2x2.2 hole 0.6x1.6: MH1(-4.32,2.975) MH4(4.32,2.975)
  oval 1.2x2.5 hole 0.6x1.9: MH2(-4.32,-0.85) MH3(4.32,-0.85)
  rect 1x2 smd: S1(-1.4,-0.85) S2(1.4,-0.85)
LEDC1608_0603N
  rect 0.8x0.8 smd: A(-0.75,0) K(0.75,0)
LEDC1608X80N_G
  rect 0.8x0.8 smd: A(-0.75,0) K(0.75,0)
MOLEX_2012670005
  rect 0.3x0.7 smd: A1(-3,7.94) A2(-2.5,7.94) A3(-2,7.94) A4(-1.5,7.94) A5(-1,7.94) A6(-0.5,7.94) A7(0.5,7.94) A8(1,7.94) A9(1.5,7.94) A10(2,7.94) A11(2.5,7.94) A12(3,7.94) B2(2.25,6.24) B3(1.75,6.24) B4(1.25,6.24) B5(0.75,6.24) B6(0.25,6.24) B7(-0.25,6.24) B8(-0.75,6.24) B9(-1.25,6.24) B10(-1.75,6.24) B11(-2.25,6.24)
  rect 0.9x0.7 smd: B1(3.05,6.24) B12(-3.05,6.24)
  oval 1.1x2.1 hole 0.6x1.6: SH1(-4.32,7.13) SH2(4.32,7.13)
  oval 1.1x3.6 hole 0.6x2.1: SH3(-4.62,1.77) SH4(4.62,1.77)
MPX1D1040L6R8
  rect 3.124x3.254 smd: 1(-4.471,0) 2(4.471,0)
NETSHORT2
  rect 0.254x0.254 smd: 1(-0.089,0) 2(0.089,0)
PG-TSDSON-8-33
  rect 0.45x0.34 smd: 1(-1.675,0.975) 2(-1.675,0.325) 3(-1.675,-0.325)
  rect 0.9x0.34 smd: 4(-1.45,-0.975)
  rect 0.65x0.34 smd: 5(1.58,-0.975) 6(1.58,-0.325) 7(1.58,0.325) 8(1.58,0.975)
QFN40P600X600X60-49N
  round 1 smd: (-3.809,-3.809) (3.809,3.809)
  oval 0.8x0.2 smd: 1(-3,2.2) 2(-3,1.8) 3(-3,1.4) 4(-3,1) 5(-3,0.6) 6(-3,0.2) 7(-3,-0.2) 8(-3,-0.6) 9(-3,-1) 10(-3,-1.4) 11(-3,-1.8) 12(-3,-2.2) 25(3,-2.2) 26(3,-1.8) 27(3,-1.4) 28(3,-1) 29(3,-0.6) 30(3,-0.2) 31(3,0.2) 32(3,0.6) 33(3,1) 34(3,1.4) 35(3,1.8) 36(3,2.2)
  oval 0.2x0.8 smd: 13(-2.2,-3) 14(-1.8,-3) 15(-1.4,-3) 16(-1,-3) 17(-0.6,-3) 18(-0.2,-3) 19(0.2,-3) 20(0.6,-3) 21(1,-3) 22(1.4,-3) 23(1.8,-3) 24(2.2,-3) 37(2.2,3) 38(1.8,3) 39(1.4,3) 40(1,3) 41(0.6,3) 42(0.2,3) 43(-0.2,3) 44(-0.6,3) 45(-1,3) 46(-1.4,3) 47(-1.8,3) 48(-2.2,3)
  rect 4.7x4.7 smd: 49(0,0)
QFN40P800X800X100-69M
  round 1 smd: (-4.809,-4.809) (4.809,4.809)
  oval 0.95x0.2 smd: 1(-4,3.2) 2(-4,2.8) 3(-4,2.4) 4(-4,2) 5(-4,1.6) 6(-4,1.2) 7(-4,0.8) 8(-4,0.4) 9(-4,0) 10(-4,-0.4) 11(-4,-0.8) 12(-4,-1.2) 13(-4,-1.6) 14(-4,-2) 15(-4,-2.4) 16(-4,-2.8) 17(-4,-3.2) 35(4,-3.2) 36(4,-2.8) 37(4,-2.4) 38(4,-2) 39(4,-1.6) 40(4,-1.2) 41(4,-0.8) 42(4,-0.4) 43(4,0) 44(4,0.4) 45(4,0.8) 46(4,1.2) 47(4,1.6) 48(4,2) 49(4,2.4) 50(4,2.8) 51(4,3.2)
  oval 0.2x0.95 smd: 18(-3.2,-4) 19(-2.8,-4) 20(-2.4,-4) 21(-2,-4) 22(-1.6,-4) 23(-1.2,-4) 24(-0.8,-4) 25(-0.4,-4) 26(0,-4) 27(0.4,-4) 28(0.8,-4) 29(1.2,-4) 30(1.6,-4) 31(2,-4) 32(2.4,-4) 33(2.8,-4) 34(3.2,-4) 52(3.2,4) 53(2.8,4) 54(2.4,4) 55(2,4) 56(1.6,4) 57(1.2,4) 58(0.8,4) 59(0.4,4) 60(0,4) 61(-0.4,4) 62(-0.8,4) 63(-1.2,4) 64(-1.6,4) 65(-2,4) 66(-2.4,4) 67(-2.8,4) 68(-3.2,4)
  rect 5.8x5.8 smd: H(0,0)
RESC1005_0402M
  rect 0.56x0.62 smd: 1(-0.54,0) 2(0.54,0)
RESC1005X40N_PEC
  rect 0.475x0.5 smd: 1(-0.513,0) 2(0.513,0)
RESC1608_0603N
  rect 0.65x0.899 smd: 1(-0.724,0) 2(0.724,0)
RESC1608X55N_A
  rect 0.8x0.95 smd: 1(-0.8,0) 2(0.8,0)
RESC1608X55N_PEC
  rect 0.65x0.899 smd: 1(-0.724,0) 2(0.724,0)
SAMTEC_FTSH-105-01-L-DV-K
  rect 0.737x2.794 smd: 1(0,0) 2(0,4.064) 3(1.27,0) 4(1.27,4.064) 5(2.54,0) 6(2.54,4.064) 7(3.81,0) 8(3.81,4.064) 9(5.08,0) 10(5.08,4.064)
SAMTEC_TSW-112-14-G-S
  rect 1.37x1.37 hole 1.02: 1(0,0)
  round 1.37 hole 1.02: 2(2.54,0) 3(5.08,0) 4(7.62,0) 5(10.16,0) 6(12.7,0) 7(15.24,0) 8(17.78,0) 9(20.32,0) 10(22.86,0) 11(25.4,0) 12(27.94,0)
SMDTP
  rect 1.8x1 smd: 1(0,0)
SOD-123_DI
  rect 0.9x0.95 smd: A(-1.575,0) K(1.575,0)
SOD-323
  rect 1.118x1.118 smd: 1(1.15,0) 2(-1.15,0)
SOD-523
  rect 0.813x0.61 smd: 1(-0.85,0) 2(0.85,0)
SODFL1608X77M
  rect 0.61x0.787 smd: A(-0.838,0) K(0.838,0)
SOP65P500X400X170-15N
  rect 0.305x0.762 smd: 1(-1.95,-2.68) 2(-1.3,-2.68) 3(-0.65,-2.68) 4(0,-2.68) 5(0.65,-2.68) 6(1.3,-2.68) 7(1.95,-2.68) 8(1.95,2.68) 9(1.3,2.68) 10(0.65,2.68) 11(0,2.68) 12(-0.65,2.68) 13(-1.3,2.68) 14(-1.95,2.68)
  rect 2.997x2.642 smd: 15(0,0)
SOT23_1_2_3
  rect 0.8x0.9 smd: 1(-0.95,-1) 2(0.95,-1) 3(0,1)
SOT95P240X111-3N
  rect 0.8x0.9 smd: 1(-0.95,-1) 2(0.95,-1) 3(0,1)
SULLINS_PPPC052LFBN-RC
  rect 1.72x1.72 hole 1.02: 1(0,0)
  round 1.72 hole 1.02: 2(0,-2.54) 3(2.54,0) 4(2.54,-2.54) 5(5.08,0) 6(5.08,-2.54) 7(7.62,0) 8(7.62,-2.54) 9(10.16,0) 10(10.16,-2.54)
SUSUMU-KRL3216
  rect 1x3.4 smd: 1(-0.95,0) 2(0.95,0)
SW_SKRPACE010
  rect 1.05x0.65 smd: 1(-2.075,1.075) 2(2.075,1.075) 3(-2.075,-1.075) 4(2.075,-1.075)
TE_1776275-2
  rect 1.8x1.8 hole 1.2: 1(0,0)
  round 1.8 hole 1.2: 2(3.5,0)
TP102C
  round 1.016 smd: 1(0,0)
TP-43R_S_B
  round 1.524 hole 1.016: 1(0,0)
TP-43R_S_R
  round 1.524 hole 1.016: 1(0,0)
unnamed#2
  oval 0.762x1.524 hole 0.762x1.524 unplated: (0,0)
WURTH_61300511121
  rect 1.7x1.7 hole 1.1: 1(0,0)
  round 1.7 hole 1.1: 2(2.54,0) 3(5.08,0) 4(7.62,0) 5(10.16,0)

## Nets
5V: J6.1 R20.1 R27.1 R28.1 TP2.1
GND: C1.2 C2.2 C3.2 C4.2 C5.2 C6.2 C7.2 C8.2 C9.2 C10.2 C11.1 C12.1 C13.1 C14.2 C15.2 C16.2 C17.2 C19.2 C20.1 C21.2 C22.2 C23.1 C24.1 C25.2 C26.2 C28.1 C29.1 C30.2 C31.1 C32.2 C33.2 C34.2 C37.2 C38.2 C39.2 C40.2 C41.2 C42.2 C43.2 C44.2 C45.2 C46.2 C47.2 C48.2 C49.2 C50.2 C51.2 C52.1 C53.1 C54.2 C55.2 C56.2 C58.2 C59.1 C60.2 C62.2 C63.2 C64.2 C65.2 C66.2 C67.2 C68.2 C69.2 C70.2 C71.2 C72.2 C73.2 C74.2 C75.1 C76.2 C77.2 C78.2 C79.2 C80.2 C81.2 C82.2 C83.2 C84.2 C88.2 C90.2 D1.1 D2.1 D3.A D10.2 D11.1 D12.1 D13.1 D14.1 D15.1 D16.1 D20.1 D21.1 D22.2 D23.1 J1.A1 J1.B1 J2.2 J3.3 J4.3 J6.3 J7.3 J8.3 J8.5 J8.7 J8.9 J9.1 J10.A1 J10.A12 J10.B1 J10.B12 J11.1 J13.6 LED1.K(CATHODE) LED2.K(CATHODE) LED4.K(CATHODE) NTC0.1 NTC1.1 Q1.1 Q4.2(S) Q10.1 Q10.2 Q10.3(S_3) Q11.1 Q11.2 Q11.3(S_3) Q14.2(S) R1.1 R6.2 R7.1 R9.1 R15.2 R16.2 R38.2 R50.1 R55.2 R57.1 R60.2 R65.1 R69.2 R70.1 R71.1 R74.2 R76.2 R78.2 R80.2 R82.2 R85.1 SW1.3 SW1.4 SW2.3 SW2.4 SW3.3 SW3.4 TP3.1 TP7.1 TP9.1 TVS1.A U1.5 U1.7 U1.8 U1.9 U1.25 U1.43 U1.45 U1.58 U1.62 U1.63 U1.H U2.4 U2.15 U3.5 U3.43 U3.49 U4.6 U4.11 U5.8
GND_EARTH1: C74.1 J1.MH1 J1.MH2 J1.MH3 J1.MH4 J1.S1 J1.S2 JMP1.1 JMP1.2 R69.1
VBUS_CTRL: Q12.4 Q13.4 U3.12
VBUS_TYPE-C: C50.1 C90.1 D5.A D19.A FB1.2 Q6.5 Q6.6 Q6.7 Q6.8 Q12.5 Q12.6 Q12.7 Q12.8 R40.1
VCC_IN: D4.K(CATHODE) D5.K(CATHODE) D17.K(CATHODE) R14.2 R41.1
AIN1: C79.1 R73.2 R74.1 SW4.3
AIN2: C80.1 R75.2 R76.1 SW5.3
AIN3: C81.1 R77.2 R78.1 SW6.3
AIN4: C82.1 R79.2 R80.1 SW7.3
B1_VDDD: C17.1 C20.2 C26.1 C28.2 C37.1 C75.2 D8.2 D9.2 J3.1 J4.1 J7.1 R3.1 R8.1 R12.2 R13.2 R18.1 R19.1 R34.2 R35.2 R36.2 R46.1 R51.1 TP4.1 U3.6 U3.22 U3.44
B1_VOUT_DC_EN_H: J6.6 R33.2 U3.25
BAT_TH_SNS: C84.1 R84.1 SW8.3
BB_IN: C48.1 C49.1 C55.1 Q13.5 Q13.6 Q13.7 Q13.8 R45.2 SP2.1
BST1: C36.2 D9.1(CATHODE) U3.1
BST2: C35.1 D8.1(CATHODE) U3.11
C1: C87.2 C88.1 R73.1 R89.1
C2: C86.2 C87.1 R75.1 R88.1
C3: C85.2 C86.1 R77.1 R87.1
C4: C85.1 C89.2 R79.1 R86.1
CC1: C22.1 D14.2 J6.4 J10.A5 U3.19
CC1_KP: J1.A5 R70.2
CC2: C25.1 D13.2 J6.5 J10.B5 U3.18
CC2_KP: J1.B5 R71.2
COMP: C38.1 R42.1 U3.13
CSNO: C27.2 R49.1 U3.16
CSPO: C27.1 R47.1 U3.17
DM_GPIO1: D12.2 DM_GPIO1.1 J6.12 J10.A7 J10.B7 U3.21
DP_GPIO0: D11.2 DP_GPIO0.1 J6.11 J10.A6 J10.B6 U3.20
HG1: HG1.1 Q8.4 U3.2
HG2: HG2.1 Q7.4 U3.10
I2C0_SCL: J7.6 R31.2 R35.1 U3.42
I2C0_SDA: J7.7 R30.2 R34.1 U3.41
I2C_SCL: J3.4 J4.4 R4.1 R31.1 U1.38
I2C_SDA: J3.6 J4.6 R30.1 R63.1 U1.39
IIN_CSN: SP1.2 U3.48
IIN_CSP: SP2.2 U3.47
IOUT_CSN: R49.2 SP4.1
IOUT_CSP: R47.2 SP3.1
KP3_UART_RX: J3.8 J4.8 R26.1 U1.21
KP3_UART_TX: J3.10 J4.10 R25.1 U1.20
KP_CLK: J2.4 U1.12
KP_DM: D1.2 J1.A7 J1.B7 R68.1
KP_DP: D2.2 J1.A6 J1.B6 R67.1
KP_IO: J2.5 U1.11
KP_VBUS_IN: D20.2 J1.A4 J1.B4(VBUS_2) Q1.3 R62.1
KP_VBUS_P: D4.A J3.2 J4.2 Q3.3 R4.2 R61.1 R62.2 R63.2 R64.2
LG1: LG1.1 Q11.4 U3.4
LG2: LG2.1 Q10.4 U3.7
LOAD_SWITCH_EN_H: J7.4 R44.1 U3.28
NTCP0: C52.2 NTC0.2 NTCP0.1 R46.2 U3.23
NTCP1: C59.2 NTC1.2 NTCP1.1 R51.2 U3.24
P1_3/AIN4: J7.2 SW7.2 U3.34
P1_4/AIN3: J7.5 SW6.2 U3.33
P1_7/BAT_TH_SNS: J6.8 SW8.2 U3.30
P5LP1_2: SW1.1 SW1.2 U1.13
P5LP1_4: R66.1 U1.15
P5LP2_2: U1.64
P5LP2_3: U1.65
P5LP2_4: U1.66
P5LP_SIO_VREF: R7.2 R8.2 U1.48
P5LP_VCCD: C9.1 C67.1 C76.1 C77.1 U1.26 U1.57
P5LP_VDD: C2.1 C3.1 C4.1 C6.1 C7.1 C8.1 C10.1 C65.1 C66.1 C68.1 C70.1 C71.1 C72.1 C73.1 J2.1 R2.1 R64.1 U1.17 U1.24 U1.35 U1.44 U1.52 U1.59 U1.67
RESET: C13.2 J3.5 J4.5 J8.10 R19.2 SW3.1 SW3.2 U1.3 U3.40(XRES)
SOURCE_BUCK_EN_H: C21.1 J7.12 R22.1 U3.39
SOURCE_FAULT_FLAG: J7.11 R54.1 U3.38
SOURCE_OUTPUT_V_SELECT: J7.8 Q14.1 R55.1 U3.29
SW_1: C36.1 L2.1 Q8.1 Q8.2 Q8.3(S_3) Q11.5 SW_1.1 U3.3
SW_2: C35.2 L2.2 Q7.1 Q7.2 Q7.3(S_3) Q10.5 SW_2.1 U3.9
SWD_CLK: J7.9 J8.4 R10.2 R12.1 U3.36
SWD_DAT: J7.10 J8.2 R11.2 R13.1 U3.37
SWDCLK: J3.7 J4.7 R10.1 U1.47
SWDIO: J3.9 J4.9 R11.1 U1.46
TH: J13.1 R83.1
UART2_RX: R25.2 SW4.1(NO)
UART2_RX/AIN1: J6.9 SW4.2 U3.31
UART2_TX: R26.2 SW5.1(NO)
UART2_TX/AIN2: J6.10 SW5.2 U3.32
UART_CTS: R9.2 U1.61
USB_V_SENSE: R1.2 R2.2 U1.19
USER_STATUS_LED: J6.7 R21.1 U3.27
USER_SWITCH: J6.2 R17.1 U3.26
VOUT: C42.1 C45.1 C46.1 C47.1 C51.1 C78.1 D22.1(CATHODE) D23.2(CATHODE) Q5.5 Q5.6 Q5.7 Q5.8 Q7.5 R39.1 R72.2 U3.8 VOUT.1
VOUT_BUCK: C16.1 C18.2 C32.1 C33.1 C60.1 L1.2 R29.1 U4.1 U4.2
VOUT_DC: C57.1 D15.2 J9.2 R48.2 R90.2 SP4.2 TP10.1
VOUT_DC_MEAS: C83.1 R81.2 R82.1 U3.35
VOUT_U2: C40.1 Q6.1(SOURCE3) Q6.2 Q6.3 R53.2 U4.3 U4.4(VOUT2)
VS_IN: C19.1 C63.1 C64.1 D17.A D18.A J11.2 R58.2 U5.1(VIN)
VTARG: C11.2 D6.A J8.1 TVS1.K
VTARG_MEAS: R3.2 R65.2 U1.32
XRES: J2.3 U1.10(X\R\E\S\)
N01675: C61.1 L1.1 U5.7 U5.9
N01977: C61.2 U5.6
N02113: C41.1 U4.7
N02139: R16.1 R22.2 R58.1 U5.2
N02147: C18.1 R15.1 R29.2 R59.1 R60.1 U5.3
N02197: R54.2 U5.5
N02205: R56.2 R57.2 U5.4
N02555: Q14.3 R59.2
N15498: C12.2 R17.2 R20.2 SW2.1 SW2.2
N16041498: C54.1 C56.1 D16.2 FB1.1 J10.A4 J10.A9 J10.B4 J10.B9(VBUS_4) TP8.1
N16043536: C53.2 D10.1 J10.SH1 J10.SH2 J10.SH3 J10.SH4 R50.2
N16124091: R53.1 U4.9
N16800802: LED3.A R18.2
N16801019: LED3.K(CATHODE) R21.2
N16919447: C31.2 R41.2 TP6.1 U3.46
N17059836: C34.1 R40.2 U3.14
N17062103: C29.2 U3.45
N17063422: C30.1 R39.2 U3.15
N17316342: C39.1 R42.2
N17354900: D18.K(CATHODE) D19.K(CATHODE) R32.2 TP5.1
N17354936: C23.2 C24.2 R32.1 U2.13
N17354948: C14.1 C15.1 R27.2 U2.9(Q)
N17368419: Q1.2(S) Q2.2(S) Q3.2(S) R5.2
N17368440: Q2.3 Q3.1 R6.1
N17368442: D3.K(CATHODE) Q2.1 R5.1
N17400441: C62.1 R56.1
N17416139: Q9.5 Q9.6 Q9.7 Q9.8 R48.1 SP3.2
N17416161: D7.1(CATHODE) Q5.1 Q5.2 Q5.3(S_3) Q9.1 Q9.2 Q9.3(S_3) R43.1
N17416246: C43.1 C44.1 Q8.5 R45.1 SP1.1
N17416442: D7.2 Q4.3 Q5.4 Q9.4 R43.2
N17416547: C57.2 C58.1
N17416846: Q4.1 R33.1 R36.1 R38.1
N17422796: Q12.1 Q12.2 Q12.3(S_3) Q13.1 Q13.2 Q13.3(S_3)
N17479997: D6.K(CATHODE) R14.1
N17481687: LED4.A R28.2
N17511481: R52.2 U4.10
N17618145: D21.2(CATHODE) R72.1
N17631535: R83.2 R84.2 R85.2 TP11.1
N17633702: C89.1 R81.1 R90.1
N17633741: J13.2 R86.2
N17633795: J13.3 R87.2
N17633797: J13.4 R88.2
N17633812: J13.5 R89.2
N17661501: R44.2 U4.8
N17663299: Q6.4 R52.1
N19965120: C1.1 U1.31
N19965125: C69.1 U1.53
N19965127: C5.1 U1.42
N19965162: R67.2 U1.22
N19965164: R68.2 U1.23
N19965683: LED2.A R61.2
N19965698: LED1.A R66.2

Pads without a net: J1 A8 B8; J8 6 8; J10 A2 A3 A8 A10 A11 B2 B3 B8 B10 B11; SW6 1; SW7 1; SW8 1; U1 1 2 4 6 14 16 18 27 28 29 30 33 34 36 37 40 41 49 50 51 54 55 56 60 68; U2 1 2 3 5 6 7 8 10 11 12 14; U4 5

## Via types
v1: diameter 0.508, hole 0.254, TOP to BOTTOM, 122 vias
v2: diameter 0.406, hole 0.203, TOP to BOTTOM, 265 vias
v3: diameter 0.457, hole 0.203, TOP to BOTTOM, 70 vias
v4: diameter 0.762, hole 0.381, TOP to BOTTOM, 348 vias
v5: diameter 0.45, hole 0.2, TOP to BOTTOM, 62 vias

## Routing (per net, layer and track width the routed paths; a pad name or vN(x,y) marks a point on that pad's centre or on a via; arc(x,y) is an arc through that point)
5V: length 28.5
  TOP w0.381: v1(77.46,54.59) R28.1 79.45,53.65 TP2.1
  TOP w0.508: J6.1 63.76,48.17 63.87,48.06 R20.1
  BOTTOM w0.381: R28.1 v1(77.46,54.59)
  BOTTOM w0.508: J6.1 63.16,47.4 71.01,47.4 74.38,50.77 78.84,50.77 79.35,51.28 v1(79.35,54.56)
GND: length 267.1
  TOP w0.203: C28.1 78.63,32.95 78.41,33.17 U3.43 78.41,37.54 v3(78.21,37.74) ; U1.43 U1.H ; U1.H 16.53,37.12 ; U1.H U1.9 ; U1.H 16.93,35.92 ; U1.63 18.93,37.92 v5(18.77,38.08) v5(17.5,38.08) 16.93,37.52 ; 16.93,37.52 16.53,37.12 ; 16.93,37.52 U1.62 ; 16.93,37.52 U1.7 ; 16.53,37.12 U1.8 ; v3(79.23,38.75) 79.64,39.17 U3.5 83.16,39.17 83.48,38.84 C75.1 ; v5(17.5,39.23) 17.5,39.66 17.73,39.89 U1.5 ; v5(13.56,36.94) 13.38,37.12 U1.25 ; 16.93,35.92 U1.45 ; 16.93,35.92 U1.58
  TOP w0.305: 73.17,13.52 v2(73.2,13.49) v2(73.2,12.96) v2(73.2,12.4) 73.2,11.87 v2(73.17,11.84) v2(73.17,11.28)
  TOP w0.381: C75.1 84.37,38.84 84.65,38.57 C37.2 v3(86.06,38.57) ; v1(18.3,28.84) 18.11,29.03 R7.1
  TOP w0.406: v3(86.06,38.57) v3(86.64,38.57)
  TOP w0.45: v1(7.15,40.19) 6.9,39.94 6.88,39.94 6.78,39.84 J1.A1 ; J1.B1 6.87,33.64 v1(7.24,33.27)
  TOP w0.508: C77.2 v1(8.78,35.17) ; J13.6 70.77,72.51 ; J13.6 69.72,71.46 ; J13.6 71.81,71.46 ; J13.6 70.77,70.42 ; 36.07,39.37 J4.3 ; J4.3 37.09,38.36 ; J4.3 38.1,39.37 ; J4.3 37.09,40.38 ; J6.3 57.32,49.01 ; J6.3 58.15,48.17 ; J6.3 56.48,48.17 ; J6.3 57.32,47.33 ; J2.2 11.46,26.34 ; J2.2 10.46,25.34 ; J2.2 12.46,25.34 ; J2.2 11.46,24.34 ; 106.2,59.38 J9.1 ; J9.1 107.26,58.33 ; J9.1 107.26,60.44 ; J9.1 108.31,59.38 ; J7.3 58.15,25.31 ; J7.3 57.32,26.15 ; J7.3 56.48,25.31 ; J11.1 74.39,5.72 ; J11.1 73.34,4.67 ; J11.1 75.44,4.67 ; J11.1 74.39,3.62 ; v3(8.83,45.92) R1.1 ; 29.47,38.36 J3.3 ; J3.3 29.47,40.38 ; J3.3 28.45,39.37 ; J3.3 30.48,39.37 ; 100.31,56.43 TP9.1 ; TP9.1 101.22,55.52 ; TP9.1 101.22,57.35 ; TP9.1 102.13,56.43 ; TP7.1 97.29,5.5 ; TP7.1 96.38,4.58 ; TP7.1 96.38,6.41 ; TP7.1 95.46,5.5 ; v1(16.7,48.44) R6.2 ; 74.47,21.33 TP3.1 ; TP3.1 76.3,21.33 ; TP3.1 75.39,22.25 ; TP3.1 75.39,20.42 ; C1.2 v1(8.81,34.13)
  TOP w0.762: 31.04,39.35 32.79,39.35 ; 31.18,31.26 32.91,31.26 ; 31.04,34.07 32.9,34.07 ; 31.03,42.21 33,42.21 ; 31.07,36.79 32.91,36.79
  GND w0.508: 96.38,4.58 TP7.1 ; TP7.1 96.38,6.41 ; TP7.1 95.46,5.5 ; TP7.1 97.29,5.5 ; 57.32,47.33 J6.3 ; J6.3 58.15,48.17 ; J6.3 57.32,49.01 ; J6.3 56.48,48.17 ; 10.46,25.34 J2.2 ; J2.2 11.46,26.34 ; J2.2 11.46,24.34 ; J2.2 12.46,25.34 ; 106.2,59.38 J9.1 ; J9.1 108.31,59.38 ; J9.1 107.26,60.44 ; J9.1 107.26,58.33 ; 100.31,56.43 TP9.1 ; TP9.1 101.22,55.52 ; TP9.1 101.22,57.35 ; TP9.1 102.13,56.43 ; J7.3 58.15,25.31 ; J7.3 56.48,25.31 ; J7.3 57.32,26.15 ; J7.3 57.32,24.47 ; 74.47,21.33 TP3.1 ; TP3.1 76.3,21.33 ; TP3.1 75.39,22.25 ; TP3.1 75.39,20.42 ; J11.1 75.44,4.67 ; J11.1 73.34,4.67 ; J11.1 74.39,5.72 ; J11.1 74.39,3.62 ; J3.3 30.48,39.37 ; J3.3 29.47,38.36 ; J3.3 29.47,40.38 ; J3.3 28.45,39.37 ; 70.77,70.42 J13.6 ; J13.6 71.81,71.46 ; J13.6 70.77,72.51 ; J13.6 69.72,71.46 ; 37.09,38.36 J4.3 ; J4.3 37.09,40.38 ; J4.3 38.1,39.37 ; J4.3 36.07,39.37
  GND w0.762: 31.06,42.21 32.93,42.21 32.93,42.21 ; 31.01,31.26 33.09,31.26 ; 30.88,34.07 33.05,34.07 ; 31.05,39.35 32.78,39.35 ; 30.93,36.79 33.04,36.79
  PWR/SIG w0.406: v2(97.79,34.47) v2(97.79,35.11) v2(97.79,35.74) 97.79,37.75 96.97,38.57 96.75,38.57 96.75,38.57 87.36,38.57 87.36,38.57 v3(86.64,38.57) v3(86.06,38.57)
  PWR/SIG w0.508: 36.07,39.37 J4.3 ; J4.3 38.1,39.37 ; J4.3 37.09,40.38 ; 74.39,3.62 J11.1 ; J11.1 74.39,5.72 ; J11.1 73.34,4.67 ; J11.1 75.44,4.67 ; 101.22,55.52 TP9.1 ; TP9.1 100.31,56.43 ; TP9.1 102.13,56.43 ; TP9.1 101.22,57.35 ; J13.6 71.81,71.46 ; J13.6 69.72,71.46 ; J13.6 70.77,72.51 ; J13.6 70.77,70.42 ; 30.48,39.37 J3.3 28.45,39.37 ; J9.1 108.31,59.38 ; J9.1 107.26,58.33 ; J9.1 106.2,59.38 ; J9.1 107.26,60.44 ; TP3.1 76.3,21.33 ; TP3.1 75.39,20.42 ; TP3.1 74.47,21.33 ; TP3.1 75.39,22.25 ; J2.2 11.46,26.34 ; J2.2 12.46,25.34 ; J2.2 11.46,24.34 ; 95.46,5.5 TP7.1 ; TP7.1 96.38,4.58 ; TP7.1 97.29,5.5 ; TP7.1 96.38,6.41 ; 58.15,25.31 J7.3 56.48,25.31 ; J6.3 58.15,48.17 ; J6.3 56.48,48.17 ; J6.3 57.32,49.01 ; J6.3 57.32,47.33
  BOTTOM w0.381: v2(104.53,8.05) 104.53,7.55 104.2,7.23 D12.1 ; v2(106.12,8.28) 105.56,8.28 105.28,8.01 D13.1 ; D14.1 v2(106.13,4.02) ; v2(104.45,3.9) 103.96,3.9 103.58,4.28 D11.1
  BOTTOM w0.45: v1(7.24,33.27) 7.17,33.27 6.3,34.14 R71.1 ; R70.1 6.64,39.68 v1(7.15,40.19)
  BOTTOM w0.457: C71.2 v1(13.21,45.12)
  BOTTOM w0.508: 58.15,48.17 J6.3 56.48,48.17 ; 28.45,39.37 J3.3 ; J3.3 29.47,40.38 ; J3.3 29.47,38.36 ; J3.3 30.48,39.37 ; C3.2 v1(12.52,28.72) ; C6.2 v1(16.64,28.89) ; J13.6 70.77,72.51 ; J13.6 71.81,71.46 ; J13.6 70.77,70.42 ; J13.6 69.72,71.46 ; 75.39,20.42 TP3.1 ; TP3.1 75.39,22.25 ; TP3.1 74.47,21.33 ; 100.31,56.43 TP9.1 ; TP9.1 102.13,56.43 ; TP9.1 101.22,57.35 ; TP9.1 101.22,55.52 ; J7.3 57.32,26.15 ; J7.3 56.48,25.31 ; J7.3 58.15,25.31 ; J4.3 38.1,39.37 ; J4.3 37.09,40.38 ; J4.3 37.09,38.36 ; J4.3 36.07,39.37 ; 95.46,5.5 TP7.1 ; TP7.1 97.29,5.5 ; TP7.1 96.38,4.58 ; TP7.1 96.38,6.41 ; 73.34,4.67 J11.1 ; J11.1 75.44,4.67 ; J11.1 74.39,3.62 ; J11.1 74.39,5.72 ; J2.2 12.46,25.34 ; J2.2 11.46,26.34 ; J2.2 11.46,24.34 ; J2.2 10.46,25.34 ; 107.26,58.33 J9.1 ; J9.1 107.26,60.44 ; J9.1 108.31,59.38 ; J9.1 106.2,59.38
  BOTTOM w0.762: 32.92,34.07 31.02,34.07 ; 33,31.26 31.1,31.26 ; 32.94,36.79 31.04,36.79 ; 32.86,39.35 30.96,39.35
  vias: v1(1.3,45.54) v1(1.6,27.64) v1(1.6,25.14) v1(5,27.54) v1(7.9,36.49) v1(8.08,42.4) v1(8.09,38.39) v1(10.1,37.94) v1(15.8,28.94) v1(20.14,42.62) v1(21.7,30.64) v1(21.9,49.09) v1(22.2,24.99) v1(23,31.74) v1(24.7,43.69) v1(25.1,49.29) v1(26.53,28.09) v1(27.4,45.89) v1(28.27,29.64) v1(29.2,24.89) v1(30.23,49.01) v1(31.15,38.6) v1(32.97,38.61) v1(64.14,48.76) v2(69.56,34.61) v2(70.19,34.61) v2(73.73,13.49) v2(73.73,12.96) v2(73.73,12.4) v2(73.73,11.84) v2(73.73,11.28) v2(74.29,11.84) v2(74.29,11.28) v2(81.35,2.03) v2(81.35,1.4) v2(81.35,0.76) v2(81.99,2.03) v2(81.99,1.4) v2(81.99,0.76) v2(82.62,2.03) v2(82.62,1.4) v2(82.62,0.76) v2(83.26,0.76) v2(83.89,0.76) v2(97.79,44) v2(97.79,43.37) v2(97.79,42.73) v2(98.4,44) v2(98.4,43.37) v2(98.4,42.73) v2(98.4,35.74) v2(98.4,35.11) v2(98.4,34.47) v3(68.73,44.15) v3(74.79,43.07) v3(76.18,41.8) v3(76.18,40.78) v3(76.18,39.77) v3(76.18,38.75) v3(77.19,41.8) v3(77.19,40.78) v3(77.19,39.77) v3(77.19,38.75) v3(77.19,37.74) v3(78.21,41.8) v3(78.21,40.78) v3(78.21,39.77) v3(78.21,38.75) v3(79.23,41.8) v3(79.23,40.78) v3(79.23,39.77) v3(79.23,37.74) v3(81.91,36.35) v3(82.24,34.91) v3(82.24,33.61) v3(82.56,35.79) v3(83.07,33.61) v3(83.37,34.87) v3(84.43,34.89) v3(85.49,34.87) v3(86.18,32.29) v3(86.2,31.43) v3(86.2,30.52) v3(86.19,29.54) v3(86.4,34.09) v3(86.75,28.85) v3(87.45,32.31) v3(87.46,31.47) v3(87.46,30.58) v3(87.82,28.7) v3(88.02,29.99) v4(33.17,29.06) v4(33.17,26.52) v4(33.28,49.14) v4(33.29,46.92) v4(33.29,44.89) v4(34.18,27.86) v4(35.21,29.06) v4(35.21,26.52) v4(36.21,27.86) v4(37.14,26.69) v4(37.24,29.06) v4(38.22,49.11) v4(38.22,47.08) v4(38.25,27.86) v4(38.56,43.63) v4(38.75,41.04) v4(38.95,37.15) v4(39.34,39.88) v4(39.29,32.89) v4(39.27,31.1) v4(39.27,29.06) v4(39.45,26.73) v4(40.2,35.78) v4(40.6,43.49) v4(40.58,41.05) v4(40.74,49.1) v4(40.74,47.07) v4(42.12,27.26) v4(42.16,29.37) v4(42.37,40.38) v4(42.62,43.63) v4(43.33,49.09) v4(43.33,47.06) v4(44.09,36.81) v4(44.1,32.84) v4(44.12,29.52) v4(44.64,39.77) v4(45.49,30.66) v4(45.49,28.12) v4(45.86,49.1) v4(45.86,47.07) v4(47,43.52) v4(46.98,41.77) v4(48.42,49.11) v4(48.42,47.07) v4(48.43,39.86) v4(48.74,28.04) v4(49.03,43.47) v4(50.97,47.26) v4(50.97,39.86) v4(51.06,43.49) v4(51.28,28.04) v4(52.51,37.38) v4(52.51,34.84) v4(53.21,43.47) v4(53.52,47.32) v4(53.89,36.06) v4(53.89,33.52) v4(55.28,42.91) v4(59.19,42.84) v4(59.19,40.3) v4(64.39,37.26) v4(64.4,35.33) v4(66.42,37.26) v4(66.42,35.23) v4(66.47,25.04) v4(67.82,26.98) v4(68.76,12.49) v4(68.76,10.46) v4(68.76,8.43) v4(68.76,6.39) v4(68.76,4.36) v4(68.94,2.27) v4(69.01,25.04) v4(69.85,1.17) v4(70.36,26.98) v4(70.63,20.79) v4(70.63,18.25) v4(71.75,1.17) v4(72.19,2.43) v4(73.04,47.52) v4(73.66,1.17) v4(74.42,56.67) v4(74.42,55.27) v4(74.73,2.43) v4(75.56,12.6) v4(75.56,10.69) v4(75.56,8.79) v4(75.61,6.93) v4(75.56,1.17) v4(77.09,49.81) v4(77.22,57.68) v4(77.47,22.12) v4(77.47,20.22) v4(77.47,8.79) v4(77.47,6.88) v4(77.47,4.98) v4(77.47,3.07) v4(77.47,1.17) v4(77.67,48.92) v4(78.36,49.81) v4(79.38,8.79) v4(79.38,2.44) v4(79.38,1.17) v4(80.01,20.22) v4(80.38,48.45) v4(81.1,57.68) v4(82.17,54.4) v4(83.17,55.66) v4(84.45,54.39) v4(84.89,51.07) v4(85.09,44.29) v4(85.22,72.41) v4(85.22,70.38) v4(85.72,14.5) v4(85.72,12.6) v4(85.72,10.69) v4(85.72,8.79) v4(85.98,49.98) v4(86.54,71.38) v4(86.49,41.33) v4(86.45,27.95) v4(86.45,25.41) v4(86.71,44.32) v4(87.49,26.66) v4(87.49,24.12) v4(87.76,72.41) v4(87.76,70.38) v4(88.27,12.6) v4(88.5,48.32) v4(88.48,44.32) v4(88.53,35.64) v4(88.51,33.4) v4(88.51,30.86) v4(88.48,27.95) v4(88.48,25.41) v4(88.48,22.87) v4(89.08,71.38) v4(90.17,62.76) v4(90.17,57.68) v4(90.3,72.41) v4(90.3,70.38) v4(91.62,71.38) v4(92.71,62.76) v4(92.71,60.22) v4(92.71,55.14) v4(92.84,72.41) v4(92.84,70.38) v4(93.98,31.01) v4(93.98,28.47) v4(94.16,71.38) v4(95.07,4.6) v4(95.25,62.76) v4(95.25,60.22) v4(95.25,53.87) v4(95.25,51.33) v4(95.38,72.41) v4(95.38,70.38) v4(96.7,71.38) v4(97.61,4.6) v4(97.79,57.68) v4(97.79,53.87) v4(97.79,51.33) v4(97.79,48.79) v4(97.79,31.01) v4(97.79,28.47) v4(97.79,25.93) v4(97.92,72.41) v4(97.92,70.38) v4(99.24,71.38) v4(100.33,53.87) v4(100.33,51.33) v4(100.33,48.79) v4(100.33,41.17) v4(100.33,38.63) v4(100.33,31.01) v4(100.46,72.41) v4(100.46,70.38) v4(101.78,71.38) v4(102.87,53.87) v4(102.87,48.79) v4(102.87,41.17) v4(102.87,38.63) v4(102.87,31.01) v4(102.87,28.47) v4(102.87,25.93) v4(103,72.41) v4(103,70.38) v4(104.32,71.38) v4(105.41,53.87) v4(105.41,41.17) v4(105.41,38.63) v4(105.41,31.01) v4(105.41,28.47) v4(105.41,25.93) v4(105.54,72.41) v4(105.54,70.38) v4(105.73,61.12) v4(105.73,59.85) v4(105.73,58.58) v4(105.73,57.31) v4(105.73,56.04) v4(106.86,71.38) v4(107,61.12) v4(107,57.31) v4(107,56.04) v4(107.95,53.87) v4(107.95,48.79) v4(107.95,41.17) v4(107.95,38.63) v4(107.95,31.01) v4(107.95,28.47) v4(107.95,25.93) v4(108.08,72.41) v4(108.08,70.38) v4(108.27,61.12) v4(108.27,57.31) v4(108.27,56.04) v4(109.54,61.12) v4(109.54,59.85) v4(109.54,58.58) v4(109.54,57.31) v4(109.54,56.04) v4(109.98,72.03) v4(110.49,70.38) v4(110.49,67.84) v4(110.49,65.3) v4(110.49,62.76) v4(110.49,53.87) v4(110.49,51.33) v4(110.49,48.79) v4(110.49,46.25) v4(110.49,43.71) v4(110.49,41.17) v4(110.49,38.63) v4(110.49,36.09) v4(110.49,33.55) v4(110.49,31.01) v4(110.49,28.47) v4(110.49,25.93) v4(110.49,23.39) v4(110.49,20.85) v4(110.49,18.31) v4(110.49,15.77) v4(110.49,13.23) v4(110.61,61.12) v4(110.61,59.85) v4(110.61,58.58) v4(110.61,57.31) v4(110.61,56.04) v5(13.56,39.23) v5(13.56,38.08) v5(13.56,35.42) v5(13.56,34.15) v5(14.83,39.23) v5(14.83,38.08) v5(14.83,36.94) v5(14.83,35.42) v5(14.83,34.15) v5(16.1,39.23) v5(16.1,38.08) v5(16.1,36.94) v5(16.23,35.42) v5(16.23,34.15) v5(17.5,36.81) v5(17.5,35.42) v5(17.5,34.15) v5(18.77,39.23) v5(18.77,36.81) v5(18.77,35.42) v5(18.77,34.15) v5(31.03,29.41)
GND_EARTH1: length 39.9
  TOP w0.381: 4.45,41.06 J1.MH1 5.77,41.89
  TOP w0.508: 2.87,30.74 JMP1.1 ; JMP1.1 3.96,31.83 ; JMP1.1 3.96,29.65 ; JMP1.1 5.05,30.74 ; J1.MH3 3.43,32.42 ; J1.MH3 1.95,31.59 ; J1.MH3 1.95,33.25 ; 4.45,32.42 J1.MH4 5.77,31.59 ; 2.87,42.74 JMP1.2 ; JMP1.2 3.96,43.83 ; JMP1.2 5.05,42.74 ; JMP1.2 3.96,41.65 ; 1.95,40.23 J1.MH2 ; J1.MH2 1.95,41.89 ; J1.MH2 3.43,41.06
  BOTTOM w0.381: 5.77,41.89 J1.MH1 4.45,41.06
  BOTTOM w0.508: 5.77,31.59 J1.MH4 ; J1.MH4 4.45,32.42 ; J1.MH4 7.1,32.42 ; 3.96,29.65 JMP1.1 ; JMP1.1 3.96,31.83 ; JMP1.1 2.87,30.74 ; JMP1.1 5.05,30.74 ; 2.87,42.74 JMP1.2 ; JMP1.2 3.96,43.83 ; JMP1.2 3.96,41.65 ; JMP1.2 5.05,42.74 ; 1.95,31.59 J1.MH3 ; J1.MH3 3.43,32.42 ; J1.MH3 1.95,33.25 ; 1.95,40.23 J1.MH2 ; J1.MH2 3.43,41.06 ; J1.MH2 1.95,41.89
VBUS_CTRL: length 48.1
  TOP w0.254: v1(81.21,42.45) U3.12 ; v2(101.29,12.64) 101.29,12.98 101.54,13.23 Q13.4 101.7,13.23 101.95,12.98 v2(101.95,12.64) ; v2(99.14,17.63) 99.14,17.29 98.88,17.04 Q12.4 98.73,17.04 98.48,17.29 v2(98.48,17.63)
  PWR/SIG w0.381: v2(101.95,12.64) v2(101.29,12.64) 100.84,13.1 100.84,17.25 100.46,17.63 v2(99.14,17.63) v2(98.48,17.63) 98.11,18 90.22,18 81.21,27.01 v1(81.21,42.45)
VBUS_TYPE-C: length 88.2
  TOP w0.381: D5.A v1(48.13,44.5) ; R40.1 v1(83.64,51.06)
  TOP w0.508: v1(78.39,51.99) 74.51,51.99 74.39,51.86 D19.A 72.29,51.86 v1(69.68,54.48)
  PWR/SIG w0.508: v4(94.04,17.04) 90.19,17.04 80.55,26.68 80.55,44.41 83.64,47.5 v1(83.64,51.06) 83.64,51.48 83.13,51.99 v1(78.39,51.99) ; v1(69.68,54.48) 69.68,51.27 67.67,49.26 66.87,49.26 62.11,44.5 v1(48.13,44.5)
  vias: v2(89.55,3.97) v2(89.55,3.39) v2(89.55,2.81) v2(90.18,3.97) v2(90.18,3.39) v2(90.18,2.81) v2(90.82,3.97) v2(90.82,3.39) v2(90.82,2.81) v2(91.45,3.97) v2(91.45,3.39) v2(91.45,2.81) v4(94.04,15.77) v4(94.04,14.5) v4(94.04,13.23) v4(95.31,17.04) v4(95.31,15.77) v4(95.31,14.5) v4(95.31,13.23) v4(96.58,17.04) v4(96.58,15.77) v4(96.58,14.5) v4(96.58,13.23)
VCC_IN: length 50.3
  TOP w0.508: v1(83.68,27.77) D17.K R41.1
  BOTTOM w0.508: v1(83.68,27.77) 83.68,28.93 73.72,38.89 46.85,38.89 45.73,40.01 v1(45.73,43.6)
AIN1: length 4.8
  TOP w0.381: SW4.3 v1(54.02,41.25)
  BOTTOM w0.381: R73.2 R74.1 C79.1 v1(54.02,41.25)
AIN2: length 5.4
  TOP w0.381: SW5.3 v1(56.64,34.99)
  BOTTOM w0.381: v1(56.64,34.99) C80.1 R76.1 R75.2
AIN3: length 4.6
  TOP w0.381: SW6.3 v1(54.02,28.74)
  BOTTOM w0.381: R77.2 R78.1 C81.1 v1(54.02,28.74)
AIN4: length 4.6
  TOP w0.381: SW7.3 v1(60.08,28.74)
  BOTTOM w0.381: v1(60.08,28.74) C82.1 R80.1 R79.2
B1_VDDD: length 274.6
  TOP w0.203: R18.1 v3(71.13,44.82) ; U3.22 76.81,44.33 76.61,44.54 75.22,44.54 74.78,44.98 C20.2 ; 79.08,34.75 78.81,35.02 U3.44 ; U3.6 82.72,39.57 82.72,39.57 83.12,39.57 83.44,39.89 C75.2
  TOP w0.381: 87.64,35.29 87.16,35.77 ; 87.16,35.77 87.64,36.24 ; 87.16,35.77 D9.2 ; 87.64,42.71 87.18,43.17 ; 87.18,43.17 87.64,43.63 ; 87.18,43.17 D8.2 ; R51.1 104.46,52.52 v3(104.43,52.49) ; TP4.1 v2(78.88,29.36) ; v2(75.88,33.12) 74.8,33.12 R34.2 ; R46.1 96.97,3.03 v2(96.84,3.16)
  TOP w0.508: v1(24.36,41.09) 24.8,40.64 28.2,40.64 J3.1 ; J7.1 63.36,25.31 63.99,25.93 R19.1 75.04,25.93 v1(75.55,26.44) ; v1(75.55,26.44) 79.6,26.44 80.11,26.95 ; v1(75.55,26.44) 75.55,26.92 74.75,27.72 R35.2 ; R12.2 v1(43.28,37.56) ; R13.2 v1(43.28,31.1) ; 87.64,40.7 87.64,39.63 ; 87.64,40.7 87.1,40.17 ; 87.64,40.7 v1(87.64,50.46) ; 87.64,39.63 87.1,40.17 ; 87.64,39.63 v1(87.64,33.26) ; 79.08,34.75 79.68,34.15 C28.2 79.68,31.2 C26.1 80.11,30.77 TP4.1 80.11,26.95 ; 80.11,26.95 v1(82.78,26.95) ; 87.1,40.17 C37.1 84.75,40.17 84.47,39.89 C75.2 ; R3.1 9.44,30.37 13.08,26.74 19.05,26.74 20.64,28.33 v1(20.64,29.56) R8.1
  PWR/SIG w0.381: v1(73.94,47.37) 71.39,44.82 v3(71.13,44.82) ; v2(78.88,29.36) 77.65,29.36 75.88,31.13 v2(75.88,33.12) ; v1(75.55,26.44) 92.13,9.86 92.13,2.4 92.51,2.02 96.46,2.02 96.84,2.4 v2(96.84,3.16)
  PWR/SIG w0.45: J4.1 35.8,40.63 33.45,40.63 v1(33.04,41.04) 33.04,41.65 32.59,42.1 31.47,42.1 31.09,41.72 v1(31.09,41.04) 30.33,41.04 J3.1
  PWR/SIG w0.508: 74.9,47.75 75.47,48.32 75.47,52.57 76.32,53.42 78.36,53.42 ; 74.9,47.75 74.52,47.37 v1(73.94,47.37) ; 74.9,47.75 74.56,48.08 v1(73.94,48.08) ; J7.1 62.4,26.15 61.89,26.66 43.96,26.66 43.28,27.34 v1(43.28,31.1) v1(43.28,37.56) ; 78.36,53.42 84.68,53.42 v1(87.64,50.46) 102.4,50.46 v3(104.43,52.49) ; 78.36,53.42 78.28,53.5 78.28,60.61 v1(72.02,66.88) ; v1(82.78,26.95) 82.78,32.04 83.99,33.26 v1(87.64,33.26)
  BOTTOM w0.508: v1(43.28,37.56) 43.28,41.17 42.54,41.91 J4.1 ; v1(24.36,41.09) 23.88,40.6 23.88,30.21 23.23,29.56 v1(20.64,29.56) ; v1(72.02,66.88) 72.06,66.88 72.07,66.87 R36.2
B1_VOUT_DC_EN_H: length 71.6
  TOP w0.188: J6.6 49.7,47 50.06,46.63 63.11,46.63 63.61,46.13 v3(63.61,44.78) ; v3(72.85,42.58) 73.47,41.97 U3.25
  BOTTOM w0.188: R33.2 69.04,68.37 68.51,67.84 68.51,50.93 66.84,49.26 63.93,49.26 63.93,49.26 49.96,49.26 49.7,48.99 J6.6 ; v3(72.85,42.58) 71.15,44.28 70.1,44.28 69.58,44.8 63.64,44.8 v3(63.61,44.78)
BAT_TH_SNS: length 3.7
  TOP w0.381: SW8.3 v1(60.08,41.25)
  BOTTOM w0.381: R84.1 61.26,41.3 C84.1 v1(60.08,41.25)
BB_IN: length 2.9
  TOP w0.14: R45.2 91.08,28.97 90.92,29.13 SP2.1
  vias: v4(103.85,17.04) v4(103.85,15.77) v4(103.85,14.5) v4(103.85,13.23) v4(105.12,17.04) v4(105.12,15.77) v4(105.12,14.5) v4(105.12,13.23) v4(106.39,17.04) v4(106.39,15.77) v4(106.39,14.5) v4(106.39,13.23)
BST1: length 4.7
  TOP w0.203: U3.1 81.51,37.57 83.31,35.77 C36.2 D9.1
BST2: length 4.6
  TOP w0.203: D8.1 C35.1 83.31,43.17 81.71,41.57 U3.11
C1: length 34.7
  TOP w0.381: v1(70.43,59.2) C88.1 C87.2 69.37,63.23 70.13,63.99 R89.1
  PWR/SIG w0.381: v1(70.43,59.2) 70.43,50.77 63.37,43.71 v1(55.57,43.71)
  BOTTOM w0.381: v1(55.57,43.71) 55.71,43.85 R73.1
C2: length 34.9
  TOP w0.381: v1(72.67,60.17) C87.1 C86.2 72.67,64.57 72.92,64.83 R88.1
  PWR/SIG w0.381: v1(72.67,60.17) 71.97,59.48 71.97,50.42 59.01,37.46 v1(58.65,37.46)
  BOTTOM w0.381: R75.1 v1(58.65,37.46)
C3: length 44.8
  TOP w0.381: v1(75.97,60.17) C85.2 C86.1 75.97,64.57 75.72,64.82 R87.1
  PWR/SIG w0.381: v1(55.62,31.2) 55.62,33.12 72.72,50.22 72.72,58.95 73.94,60.17 v1(75.97,60.17)
  BOTTOM w0.381: R77.1 v1(55.62,31.2)
